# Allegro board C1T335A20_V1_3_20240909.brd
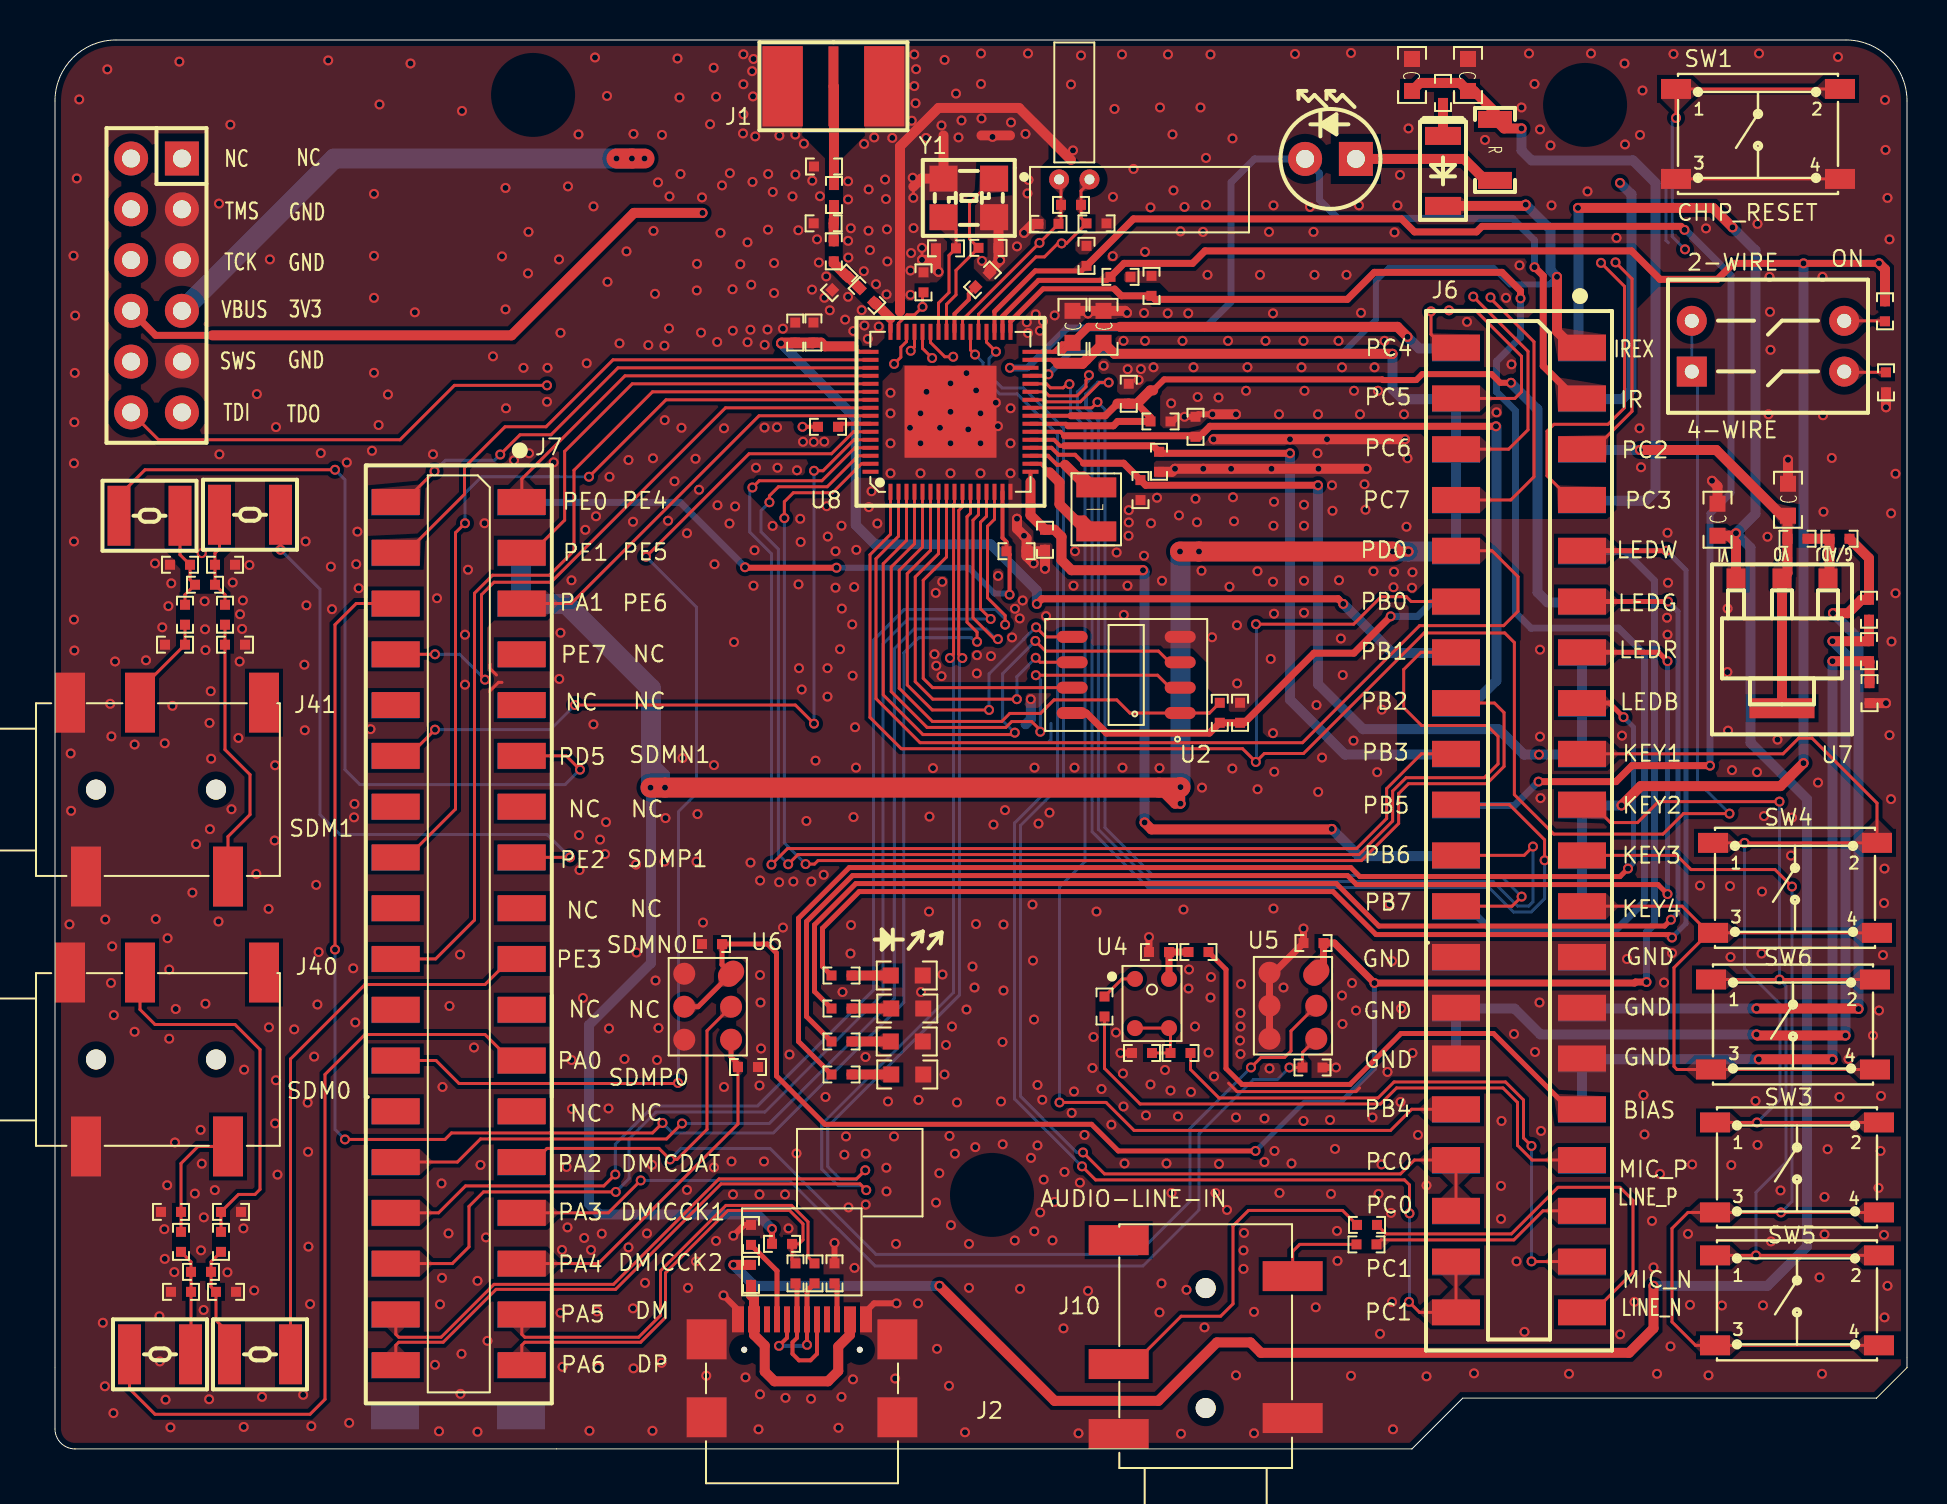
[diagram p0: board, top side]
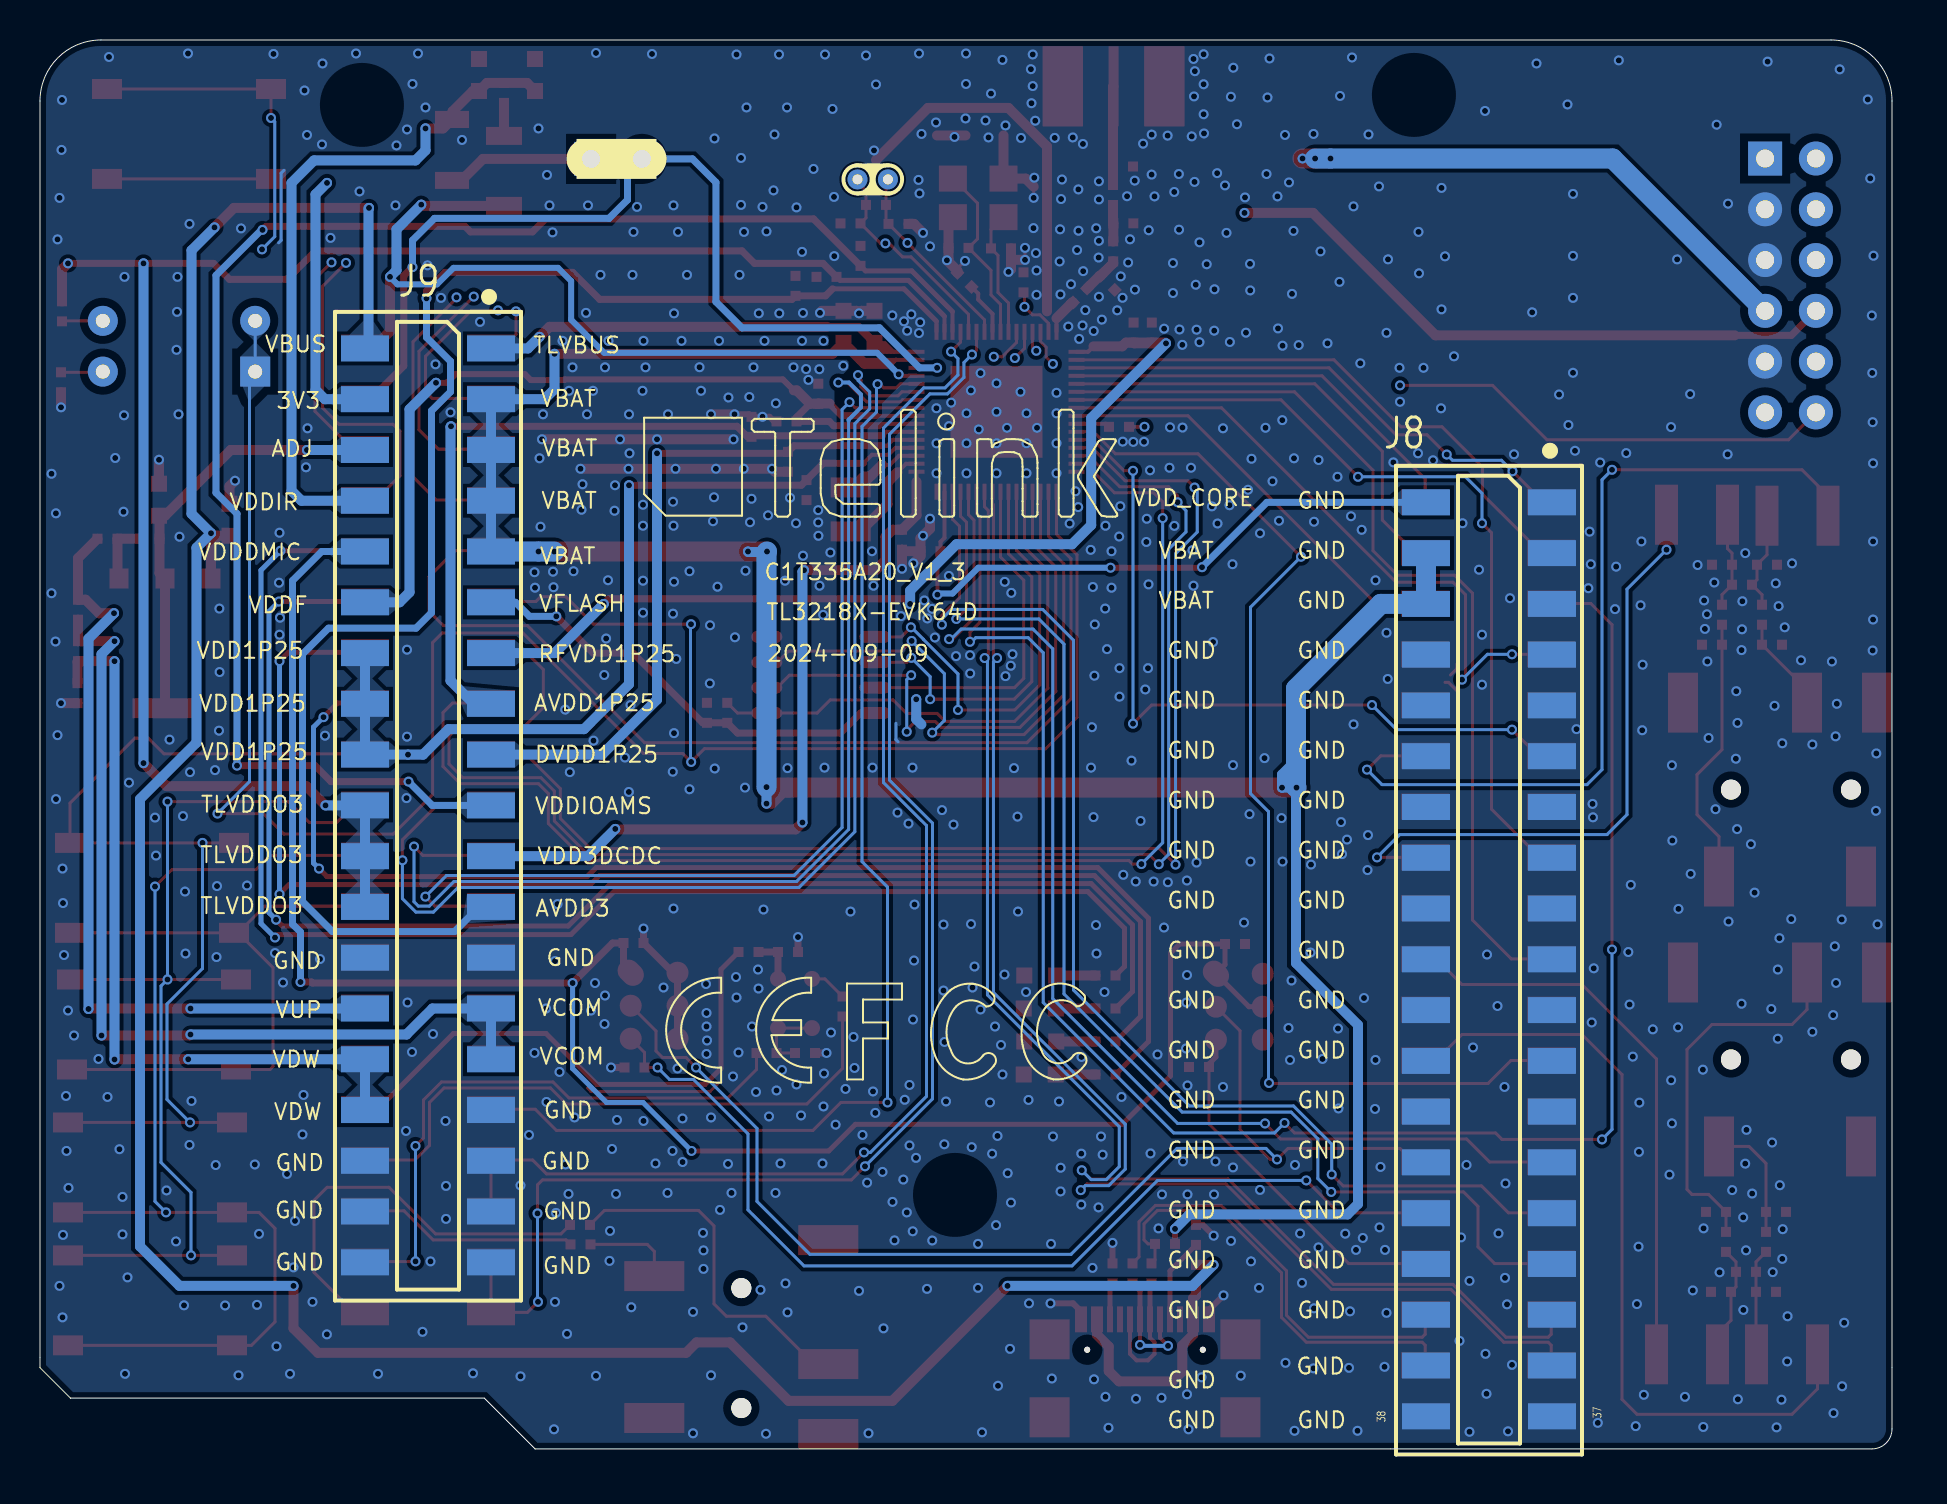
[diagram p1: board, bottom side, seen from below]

Outline 92.6 x 70.48 mm; copper layers: TOP, GND, POWER, BOTTOM. Coordinates in mm from the lower left corner of the outline.
Outline path: 0,67.43 0,1 arc(0.29,0.29) 1,0 67.85,0 70.39,2.54 91.08,2.54 92.6,4.06 92.6,67.43 arc(91.71,69.59) 89.55,70.48 3.05,70.48 arc(0.89,69.59) 0,67.43

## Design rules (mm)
constraint set DEFAULT: min track width 0.15, pair gap 0.1
net group DP1: nets TL_DM TL_DP
net group DP2: nets TL_PA5_DM TL_PA6_DP

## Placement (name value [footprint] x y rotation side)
C1  220pF  [0402]  40.6 57.7 135 top
C2  NC  [0402]  39.22 58.33 225 top
C3  1.5pF  [0402]  38.43 61.31 180 top
C5  NC  [0402]  44.55 60.06 0 top
C6  NC  [0402]  46.67 60.08 180 top
C8  0.1uF  [0402]  37.01 55.84 90 top
C9  2.2uF  [0402]  37.92 55.84 90 top
C12  2.2uF  [0402]  48.08 44.91 0 top
C15  1uF  [0402]  54.83 58.18 90 top
C18  1uF  [0402]  53.27 58.63 0 top
C21  NC  [0402]  52.08 61.31 180 top
C22  NC  [0402]  49.67 61.28 0 top
C23  1uF  [0402]  49.5 45.48 270 top
C24  1uF  [0402]  53.69 52.78 90 top
C26  NC/1uF  [0402]  55.27 51.4 0 top
C27  NC/1uF  [0402]  55.2 49.38 270 top
C28  4.7uF  [0402]  57.02 51.13 90 top
C30  1uF  [0402]  54.27 47.96 270 top
C33  1uF  [0402]  59.25 36.82 90 top
C36  10uF  [0603C]  70.65 68.73 270 top
C37  10uF  [0603C]  67.85 68.73 270 top
C38  10nF  [0402]  52.48 22.13 270 top
C39  1uF  [0402]  55.2 24.86 180 top
C41  0.1uF  [0402]  62.92 25.31 180 top
C42  0.1uF  [0402]  32.85 25.26 180 top
C43  10uF  [0603C]  83.12 46.48 90 top
C44  10uF  [0603C]  86.65 47.48 90 top
C45  2pF  [0402]  38.45 64.15 180 top
C47  1uF  [0402]  46.38 58.48 45 top
C48  10uF  [0603C]  52.42 56.13 90 top
C49  10uF  [0603C]  50.88 56.13 90 top
C50  1uF  [0402]  51.58 59.68 90 top
C51  10nF  [0402]  65.58 10.23 0 top
C52  10nF  [0402]  65.6 11.21 0 top
C53  1uF  [0402]  43.42 58.36 90 top
C69  NC  [0402]  8.55 7.86 180 top
C73  220nF  [0402]  7.3 8.86 180 top
C75  10pF  [0402]  8.8 11.86 180 top
C76  10pF  [0402]  5.8 11.86 180 top
C115  NC  [0402]  6.3 7.86 180 top
C116  NC  [0402]  8.5 44.23 0 top
C117  NC  [0402]  6.25 44.23 0 top
C118  10pF  [0402]  6 40.23 0 top
C119  10pF  [0402]  9 40.23 0 top
C120  220nF  [0402]  7.5 43.23 0 top
C121  10nF  [0402]  56.27 19.81 0 top
D1  Red  [0603-LED]  42.59 20.38 0 top
D2  White  [0603-LED]  42.59 23.68 0 top
D3  Green  [0603-LED]  42.61 22.03 0 top
D4  Blue  [0603-LED]  42.61 18.73 0 top
D5  LED_IR  [LED_TH_2P54MM_2PIN]  63.77 64.53 0 top
D6  1N4148  [SOD80]  69.4 63.93 270 top
J1  RFIN  [SMA-H]  38.92 68.16 90 top
J2  Type-C 16pin  [TYPE_C_CQ_105PWB]  37.35 5.48 0 top
J3  DIP_2X2  [DIPSWITCH_2P54_7P62_2X2]  85.65 55.16 270 top
J4  JTAG  [HDR254F-2X6X850]  6.35 51.85 90 top
J6  HEADER 20x2  [SMD254M-2X20_RX1_30Y2_40]  73.2 28.42 90 top
J7  HEADER 18X2  [SMD254M-2X18_RX1_30Y2_40]  20.19 20.7 90 top
J8  HEADER 19x2  [HDR2X19-2R54-SM-M]  20.15 24.45 90 bottom
J9  HEADER 19x2  [HDR2X19-2R54-SM-M]  73.2 32.15 90 bottom
J10  AIL1  [PJ-327]  57.53 -0.96 180 top
J40  PJ327  [PJ-327]  -0.95 19.48 90 top
J41  PJ327  [PJ-327]  -0.95 32.98 90 top
L1  2.2nH  [0402]  38.94 59.91 90 top
L2  6.8uH  [0805L_0717]  52.06 47 90 top
L3  2.4nH  [0402]  38.95 62.72 90 top
L15  150uH  [INDM3025X25]  5.25 4.73 0 top
L16  150uH  [INDM3025X25]  10.25 4.73 180 top
L17  150uH  [INDM3025X25]  9.75 46.73 180 top
L18  150uH  [INDM3025X25]  4.72 46.68 0 top
R1  NC  [0402]  50.8 62.23 180 top
R2  NC/1.5K  [0402]  36.35 10.26 180 top
R3  4.7K  [0402]  58.24 36.82 90 top
R4  33  [0402]  37.02 8.78 90 top
R5  5.1K  [0402]  34.8 10.71 270 top
R6  33  [0402]  37.98 8.78 90 top
R7  1K  [0402]  91.5 56.91 90 top
R8  1M  [0402]  91.55 53.36 270 top
R9  2R  [0402]  34.8 8.71 270 top
R10  5.1K  [0402]  38.98 8.78 270 top
R11  68R  [0402]  38.65 51.13 180 top
R12  1K  [0402]  39.33 20.38 0 top
R13  1K  [0402]  39.33 18.73 0 top
R14  1K  [0402]  39.33 23.68 0 top
R15  1K  [0402]  39.33 22.03 0 top
R16  1R  [1206R]  72 64.98 270 top
R17  0R  [0402]  69.4 67.83 270 top
R18  2.2K  [0402]  57.17 24.86 180 top
R27  100K  [0402]  62.88 19.08 180 top
R28  100K  [0402]  34.65 19.11 180 top
R29  430R  [0402]  89.22 45.53 0 top
R30  1.15K  [0402]  90.7 41.98 270 top
R31  787R  [0402]  90.7 39.91 270 top
R32  464R  [0402]  90.72 37.81 270 top
R33  1K  [0402]  87.12 45.53 180 top
R34  2.2K  [0402]  54.35 19.81 0 top
R40  33  [0402R]  6.3 10.36 90 top
R41  33  [0402R]  8.3 10.36 90 top
R42  33  [0402R]  8.5 41.73 270 top
R43  33  [0402R]  6.5 41.73 270 top
SW1  SW4PIN_4.5x4.5  [SW_6X6_SMD]  85.15 65.78 0 top
SW3  SW4PIN_4.5x4.5  [SW_6X6_SMD]  87.1 14.08 0 top
SW4  SW4PIN_4.5x4.5  [SW_6X6_SMD]  87 28.07 0 top
SW5  SW4PIN_4.5x4.5  [SW_6X6_SMD]  87.1 7.43 0 top
SW6  SW4PIN_4.5x4.5  [SW_6X6_SMD]  86.9 21.23 0 top
U2  P25Q16SUFWF  [W25X10_20_40BL]  53.56 38.72 90 top
U4  WMM7037AT2  [GA_BFA423_A83]  54.85 22.28 0 top
U5  WMM7047DTFN0  [DMIC_SPM0423HM4H-WB]  61.89 22.17 270 top
U6  WMM7047DTFN0  [DMIC_SPM0423HM4H-WB]  32.63 22.12 270 top
U7  LM1117-ADJ  [SOT-223]  86.35 40.05 180 top
U8  TL3218X  [QFN_8X8_64PIN_0P4_4P50X4P50]  44.77 51.88 90 top
Y1  24MHz-12pF-+/-10ppm  [OSCCC250X320X110]  45.69 62.58 270 top
Y2  NC/32.768K  [OSC_2X6]  50.97 67.51 270 top

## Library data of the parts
C1-C3 C21 C22 C45 = C1608_NC
C5 C6 C69 C115-C117 = C1005_NC
C8 C9 C12 C15 C18 C23 C24 C26-C28 C30 C33 C36-C39 C47-C53 C121 = C1005X5R1C104K
C41 C42 = C1005X5R1C104K_1
C43 = C1608X5R0J106M
C44 = C1608X5R1C105M
C73 C120 = C1005X5R1C224M
C75 C76 C118 C119 = C1005C0G1H100D
D1-D4 = 0603D_Green
D5 = Led_Th_3mm_1: User Part Number: partnum; Tolerance: RichardLC
D6 = Diode_1N4148
J1 = SMA_JACK_2
J2 = Type-C 16pin_0
J3 = HEADER 2X2_0: User Part Number: pn; Tolerance: RichardLC
J4 = HEADER 6X2: User Part Number: pn; Tolerance: RichardLC
J6 = HEADER 20x2/M: Tolerance: RichardLC
J7 = HEADER 18X2: Tolerance: RichardLC
J8 J9 = HEADER 19x2: Tolerance: RichardLC
J10 J40 J41 = PJ327_2
L1 L3 = MLK1608_000R
L2 = IND_0
L15-L18 = IND_150uH_3025
R1 R11 = RS0603K102JT
R2 = RS0402K152JT
R3 R7 R8 R18 R27 R28 R34 = RS0402K104JT
R4-R6 R9 R10 = RS0402K330JT: room: USB
R12-R15 R17 = RS0402K102JT
R16 = RS0402K102JT: User Part Number: pn; Tolerance: RichardLC
R29-R33 = RS0603K104JT
R40-R43 = RS0402K330JT
SW1 SW3-SW6 = SW_6X6_SMD_0
U2 = GD25LD40C_0: Tolerance: RichardLC
U4 = MULPS4CX-RM5_0
U5 U6 = LD1117/SO_0
U7 = XC62FP3302_0.3V_SOT-89
U8 = TL321X_0
Y1 = CRYSTAL4/SM_0: Tolerance: RichardLC
Y2 = OSC_2x6_2pin_16Mhz

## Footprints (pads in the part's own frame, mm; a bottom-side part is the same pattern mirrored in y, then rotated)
0402
  rect 0.5x0.5 smd: 1(-0.5,0) 2(0.5,0)
0402R
  rect 0.5x0.5 smd: 1(-0.5,0) 2(0.5,0)
0603-LED
  rect 0.8x0.8 smd: A(-0.8,0) C(0.8,0)
0603C
  rect 0.8x0.8 smd: 1(-0.8,0) 2(0.8,0)
0805L_0717
  rect 1x2 smd: 1(1.1,0) 2(-1.1,0)
1206R
  rect 0.85x1.7 smd: 1(-1.525,0) 2(1.525,0)
DIPSWITCH_2P54_7P62_2X2
  rect 1.5x1.5 hole 0.7: 1(1.27,-3.81)
  round 1.5 hole 0.7: 2(1.27,3.81) 3(-1.27,-3.81) 4(-1.27,3.81)
DMIC_SPM0423HM4H-WB
  round 1.1 smd: 1(-1.65,-1.17) 2(0,-1.17) 3(1.65,-1.17) 4(1.65,1.17) 5(0,1.17)
  oval 1.4x1.1 smd rot 135: 6(-1.65,1.17)
GA_BFA423_A83
  round 0.8 smd: 1(-0.85,1.23) 2(-0.85,-1.23) 3(0.85,-1.23) 4(0.85,1.23)
HDR2X19-2R54-SM-M
  rect 1.3x2.4 smd: 1(22.9,-3.15) 2(22.9,3.15) 3(20.36,-3.15) 4(20.36,3.15) 5(17.82,-3.15) 6(17.82,3.15) 7(15.28,-3.15) 8(15.28,3.15) 9(12.74,-3.15) 10(12.74,3.15) 11(10.2,-3.15) 12(10.2,3.15) 13(7.66,-3.15) 14(7.66,3.15) 15(5.12,-3.15) 16(5.12,3.15) 17(2.58,-3.15) 18(2.58,3.15) 19(0.04,-3.15) 20(0.04,3.15) 21(-2.5,-3.15) 22(-2.5,3.15) 23(-5.04,-3.15) 24(-5.04,3.15) 25(-7.58,-3.15) 26(-7.58,3.15) 27(-10.12,-3.15) 28(-10.12,3.15) 29(-12.66,-3.15) 30(-12.66,3.15) 31(-15.2,-3.15) 32(-15.2,3.15) 33(-17.74,-3.15) 34(-17.74,3.15) 35(-20.28,-3.15) 36(-20.28,3.15) 37(-22.82,-3.15) 38(-22.82,3.15)
HDR254F-2X6X850
  rect 1.7x1.7 hole 0.9: 1(12.7,0)
  round 1.7 hole 0.9: 2(12.7,2.54) 3(10.16,0) 4(10.16,2.54) 5(7.62,0) 6(7.62,2.54) 7(5.08,0) 8(5.08,2.54) 9(2.54,0) 10(2.54,2.54) 11(0,0) 12(0,2.54)
INDM3025X25
  rect 1.15x3 smd: 1(-1.525,0) 2(1.525,0)
LED_TH_2P54MM_2PIN
  rect 1.7x1.7 hole 0.9: A(1.27,0)
  round 1.7 hole 0.9: C(-1.27,0)
OSC_2X6
  round 1 hole 0.5: 1(4,0.76) 2(4,-0.76)
OSCCC250X320X110
  rect 1.3x1.4 smd: 1(-0.965,1.265) 2(-0.965,-1.265) 3(0.965,-1.265) 4(0.965,1.265)
PJ-327
  round 1 hole 1 unplated: (0,-3) (0,-9)
  rect 3x1.5 smd: 1(-4.35,-2.5) 2(4.35,-5.2) 3(-4.35,-9.6) 4(4.35,-11.4) 5(4.35,-1.7)
QFN_8X8_64PIN_0P4_4P50X4P50
  rect 0.8x0.2 smd: 1(-4,3) 2(-4,2.6) 3(-4,2.2) 4(-4,1.8) 5(-4,1.4) 6(-4,1) 7(-4,0.6) 8(-4,0.2) 9(-4,-0.2) 10(-4,-0.6) 11(-4,-1) 12(-4,-1.4) 13(-4,-1.8) 14(-4,-2.2) 15(-4,-2.6) 16(-4,-3) 33(4,-3) 34(4,-2.6) 35(4,-2.2) 36(4,-1.8) 37(4,-1.4) 38(4,-1) 39(4,-0.6) 40(4,-0.2) 41(4,0.2) 42(4,0.6) 43(4,1) 44(4,1.4) 45(4,1.8) 46(4,2.2) 47(4,2.6) 48(4,3)
  rect 0.2x0.8 smd: 17(-3,-4) 18(-2.6,-4) 19(-2.2,-4) 20(-1.8,-4) 21(-1.4,-4) 22(-1,-4) 23(-0.6,-4) 24(-0.2,-4) 25(0.2,-4) 26(0.6,-4) 27(1,-4) 28(1.4,-4) 29(1.8,-4) 30(2.2,-4) 31(2.6,-4) 32(3,-4) 49(3,4) 50(2.6,4) 51(2.2,4) 52(1.8,4) 53(1.4,4) 54(1,4) 55(0.6,4) 56(0.2,4) 57(-0.2,4) 58(-0.6,4) 59(-1,4) 60(-1.4,4) 61(-1.8,4) 62(-2.2,4) 63(-2.6,4) 64(-3,4)
  rect 4.6x4.6 smd: 65(0,0)
SMA-H
  rect 4x0.5 smd: 1(0,0)
  rect 4x2 smd: 2(0,-2.54) 3(0,2.54) 4(0,-2.54) 5(0,2.54)
SMD254M-2X18_RX1_30Y2_40
  rect 1.3x2.4 smd: 1(26.67,-3.15) 2(26.67,3.15) 3(24.13,-3.15) 4(24.13,3.15) 5(21.59,-3.15) 6(21.59,3.15) 7(19.05,-3.15) 8(19.05,3.15) 9(16.51,-3.15) 10(16.51,3.15) 11(13.97,-3.15) 12(13.97,3.15) 13(11.43,-3.15) 14(11.43,3.15) 15(8.89,-3.15) 16(8.89,3.15) 17(6.35,-3.15) 18(6.35,3.15) 19(3.81,-3.15) 20(3.81,3.15) 21(1.27,-3.15) 22(1.27,3.15) 23(-1.27,-3.15) 24(-1.27,3.15) 25(-3.81,-3.15) 26(-3.81,3.15) 27(-6.35,-3.15) 28(-6.35,3.15) 29(-8.89,-3.15) 30(-8.89,3.15) 31(-11.43,-3.15) 32(-11.43,3.15) 33(-13.97,-3.15) 34(-13.97,3.15) 35(-16.51,-3.15) 36(-16.51,3.15)
SMD254M-2X20_RX1_30Y2_40
  rect 1.3x2.4 smd: 1(26.67,-3.15) 2(26.67,3.15) 3(24.13,-3.15) 4(24.13,3.15) 5(21.59,-3.15) 6(21.59,3.15) 7(19.05,-3.15) 8(19.05,3.15) 9(16.51,-3.15) 10(16.51,3.15) 11(13.97,-3.15) 12(13.97,3.15) 13(11.43,-3.15) 14(11.43,3.15) 15(8.89,-3.15) 16(8.89,3.15) 17(6.35,-3.15) 18(6.35,3.15) 19(3.81,-3.15) 20(3.81,3.15) 21(1.27,-3.15) 22(1.27,3.15) 23(-1.27,-3.15) 24(-1.27,3.15) 25(-3.81,-3.15) 26(-3.81,3.15) 27(-6.35,-3.15) 28(-6.35,3.15) 29(-8.89,-3.15) 30(-8.89,3.15) 31(-11.43,-3.15) 32(-11.43,3.15) 33(-13.97,-3.15) 34(-13.97,3.15) 35(-16.51,-3.15) 36(-16.51,3.15) 37(-19.05,-3.15) 38(-19.05,3.15) 39(-21.59,-3.15) 40(-21.59,3.15)
SOD80
  rect 0.9x1.8 smd: A(-1.75,0) C(1.75,0)
SOT-223
  rect 0.95x1 smd: 1(-2.3,-3.495) 2(0,-3.495) 3(2.3,-3.495)
  rect 3.25x1 smd: 4(0,2.995)
SW_6X6_SMD
  rect 1.5x1 smd: 1(-4.1,2.25) 2(4.1,2.25) 3(-4.1,-2.25) 4(4.1,-2.25)
TYPE_C_CQ_105PWB
  round 0.3 hole 0.7 unplated: (-2.89,-0.52) (2.89,-0.52)
  rect 2x2 smd: 13(-4.77,0) 14(4.77,0) 15(-4.77,-3.9) 16(4.77,-3.9)
  rect 0.6x1.3 smd: A1B12(-3.2,1) A4B9(-2.4,1) B1A12(3.2,1) B4A9(2.4,1)
  rect 0.3x1.3 smd: A5(-1.25,1) A6(-0.25,1) A7(0.25,1) A8(1.25,1) B5(1.75,1) B6(0.75,1) B7(-0.75,1) B8(-1.75,1)
W25X10_20_40BL
  oval 0.6x1.55 smd: 1(-1.905,-2.7) 2(-0.635,-2.7) 3(0.635,-2.7) 4(1.905,-2.7) 5(1.905,2.7) 6(0.635,2.7) 7(-0.635,2.7) 8(-1.905,2.7)

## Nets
GND: C2.2 C3.2 C5.1 C6.1 C8.2 C9.2 C12.2 C15.2 C18.2 C21.1 C22.1 C23.2 C24.2 C26.2 C27.2 C28.2 C30.2 C33.2 C36.1 C37.1 C39.2 C41.2 C42.2 C43.2 C44.2 C45.2 C47.2 C48.2 C49.2 C50.2 C53.2 C69.1 C75.1 C76.2 C115.2 C116.2 C117.1 C118.1 C119.2 D1.C(CATHODE) D2.C(CATHODE) D3.C(CATHODE) D4.C(CATHODE) J1.2 J1.3 J1.4 J1.5 J2.13 J2.14 J2.15 J2.16 J2.A1B12 J2.B1A12 J4.3 J4.5 J4.9 J6.25 J6.26 J6.27 J6.28 J6.29 J6.30 J8.1 J8.3 J8.5 J8.7 J8.8 J8.9 J8.10 J8.11 J8.12 J8.13 J8.14 J8.15 J8.16 J8.17 J8.18 J8.19 J8.20 J8.21 J8.22 J8.23 J8.24 J8.25 J8.26 J8.27 J8.28 J8.29 J8.30 J8.31 J8.32 J8.33 J8.34 J8.35 J8.36 J8.37 J8.38 J9.25 J9.26 J9.31 J9.33 J9.34 J9.35 J9.36 J9.37 J9.38 J10.1 J10.5 J40.1 J40.5 J41.1 J41.5 R5.1 R8.2 R10.1 R27.1 R28.1 R32.2 R34.1 SW1.3 SW1.4 U2.4 U5.1 U5.2(SE) U5.3 U6.1 U6.3 U8.16 U8.65 Y1.2 Y1.4
VBAT_ADJ: C44.1 J9.6 R33.2 U7.2 U7.4(VOUT#4)
VBUS: C43.1 J4.8 J9.2 R9.1 U7.3
AIN_LINEIN_N: C52.2 J6.39
AIN_LINEIN_P: C51.2 J6.35
AIN_MIC_N: C121.2 J6.37
AIN_MIC_P: C38.2 J6.33
BEVK_SWS: J4.10 R11.2
DM: J2.A7 J2.B7 R6.1
DMICCK1: J7.29 R27.2 U5.4
DMICCK2: J7.31 R28.2 U6.4
DMICDAT: J7.27 U5.5 U6.5
DP: J2.A6 J2.B6 R4.1
EXT_3V3: J4.7 J9.4
LED_B: J6.15 R13.1
LED_G: J6.11 R15.1
LED_R: J6.13 R12.1
LED_W: J6.9 R14.1
MICBIAS: J6.31 R18.1
TL_ANT: C1.1 U8.48
TL_AVDD1P25: C28.1 J9.15 U8.22
TL_AVDD3: C15.1 J9.23 U8.33
TL_DM: J7.33 R6.2
TL_DP: J7.35 R2.1 R4.2
TL_DVDD1P25: C27.1 J9.17 U8.21
TL_FLASH: C33.1 J9.11 R3.1 U2.8
TL_IR: D5.C(CATHODE) J6.3 U8.30
TL_IR_EX_DIOD: D6.C J6.1 U8.29
TL_KEY1: J6.17 SW3.1 SW3.2 SW4.1 SW4.2
TL_KEY2: J6.19 SW5.1 SW5.2 SW6.1 SW6.2
TL_KEY3: J6.21 SW3.3 SW3.4 SW5.3 SW5.4
TL_KEY4: J6.23 SW4.3 SW4.4 SW6.3 SW6.4
TL_PA0: J7.24 U8.59
TL_PA1: J7.6 U8.11
TL_PA2: J7.28 U8.12
TL_PA3: J7.30 U8.14
TL_PA4: J7.32 U8.13
TL_PA5_DM: J7.34 U8.10
TL_PA6_DP: J7.36 U8.9
TL_PA7_SWS: R11.1 U8.58
TL_PB0: J3.1 J3.3 J6.12 U8.1
TL_PB1: J6.14 U8.62
TL_PB2: J6.16 U8.63
TL_PB3: J6.18 U8.61
TL_PB4: J6.32 U8.28
TL_PB5: J6.20 U8.27
TL_PB6: J6.22 U8.26
TL_PB7: J6.24 U8.25
TL_PC0_AUDIO_P: J6.34 J6.36 U8.36
TL_PC1_AUDIO_N: J6.38 J6.40 U8.38
TL_PC2_32K: C21.2 J6.5 R1.1 U8.37 Y2.1
TL_PC3_32K: C22.2 J6.7 R1.2 U8.39 Y2.2
TL_PC4_TDI: J4.12 J6.2 U8.43
TL_PC5_TDO: J4.11 J6.4 U8.44
TL_PC6_TMS: J4.4 J6.6 U8.46
TL_PC7_TCK: J4.6 J6.8 U8.45
TL_PD0: J6.10 U8.2
TL_PD5: J7.12 U8.60
TL_PE0: J7.2 U8.51
TL_PE1: J7.4 U8.50
TL_PE2: J7.16 U8.55
TL_PE3: J7.20 U8.54
TL_PE4: J7.1 U8.52
TL_PE5: J7.3 U8.53
TL_PE6: J7.5 U8.57
TL_PE7: J7.8 U8.56
TL_PF0_MOSI: U2.5 U8.6
TL_PF1_MCLK: U2.6 U8.7
TL_PF2_MSIO3: U2.7 U8.8
TL_PF3_MSCN: R3.2 U2.1 U8.5
TL_PF4_MISO: U2.2 U8.4
TL_PF5_MSIO2: U2.3(W\P\/IO2) U8.3
TL_RFVDD_1P25: C8.1 C9.1 J9.13 U8.49
TL_SDMN0: J7.19 L16.1
TL_SDMN1: J7.11 L18.1
TL_SDMP0: J7.23 L15.1
TL_SDMP1: J7.15 L17.1
TL_VBAT: C48.1 J8.4 J8.6 J9.3 J9.5 J9.7 J9.9 R2.2 U8.31
TL_VBUS: C49.1 J9.1 U8.32
TL_VDCDCF: C24.1 C26.1 J9.12 U8.23 U8.24
TL_VDD1P25: C30.1 J9.14 J9.16 J9.18 U8.20
TL_VDD3_DCDC: C23.1 J9.21 U8.17
TL_VDD_DMIC: C41.1 C42.1 J9.10 U5.6 U6.2(SE) U6.6
TL_VDD_IR: C36.2 C37.2 J9.8 R16.1 R17.1
TL_VDDCORE: C12.1 J8.2 U8.15
TL_VDDIO_AMS: C50.1 J9.19 U8.35
TL_VDDO3: C18.1 J9.20 J9.22 J9.24 R7.2 U8.34
TL_XC1: C5.2 U8.42 Y1.3
TL_XC2: C6.2 U8.41(XC2) Y1.1
USB_VBUS: J2.A4B9 J2.B4A9(VBUS#B4A9) R9.2
VCOM: J9.27 J9.29 R30.2 R31.1
VDW: J9.30 J9.32 R31.2 R32.1
VUP: J9.28 R29.2 R30.1
N20028206: R29.1 R33.1 U7.1
N20230742: D1.A R12.2
N20265888: C45.1 J1.1 L3.2
N20271178: D5.A R16.2
N20271193: D6.A R17.2
N20290987: L2.1 U8.19
N20305837: J2.A5 R5.2
N20305839: J2.B5 R10.2
N20310970: C1.2 C2.1 L1.1
N20310976: C3.1 L1.2 L3.1
N20338940: C53.1 SW1.1 SW1.2 U8.47
N20339485: C47.1 U8.40
N20340397: L2.2 U8.18
N20354870: C51.1 J10.3
N20355410: C39.1 R18.2 U4.4(VDD)
N20355416: C121.1 R34.2 U4.2 U4.3
N20355524: C38.1 U4.1
N20367047: C52.1 J10.2
N20394676: C116.1 C120.2 L17.2 R42.1
N20394683: C117.2 C120.1 L18.2 R43.1
N20394695: C119.1 J41.3 R42.2
N20394699: C118.2 J41.2 R43.2
N20394813: C73.2 C115.1 L15.2 R40.1
N20394820: C69.2 C73.1 L16.2 R41.1
N20394832: C76.1 J40.3 R40.2
N20394836: C75.2 J40.2 R41.2
N20397613: D2.A R14.2
N20397615: D3.A R15.2
N20397764: D4.A R13.2
N202309440: J3.2 R8.1
N202309690: J3.4 R7.1

Pads without a net: J2 A8 B8; J4 1 2; J7 7 9 10 13 14 17 18 21 22 25 26; J10 4; J40 4; J41 4; U8 64

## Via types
v1: diameter 0.5, hole 0.3, TOP to BOTTOM, 1088 vias

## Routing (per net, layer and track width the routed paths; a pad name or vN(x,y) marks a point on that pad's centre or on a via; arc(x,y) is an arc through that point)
GND: length 84.5
  TOP w0.15: 21.75,39.26 21.75,39.04 22.08,38.71 ; v1(42.92,62.58) 42.92,63.15 ; SW1.3 SW1.4 ; 65.23,18.05 65.05,17.87 59.1,17.87 58.68,18.29 ; 22.35,38.35 22.18,38.35 21.73,37.89 ; 46.73,58.93 46.73,59.05 v1(46.35,59.43) ; v1(43.35,59.48) v1(43.35,60.08)
  TOP w0.3: R5.1 34.46,11.21 v1(33.92,10.67) ; C26.2 55.89,51.4 56.12,51.63 v1(56.48,51.63) C28.2 57.15,51.76 v1(57.88,51.76) ; v1(42.08,7.28) 40.95,7.28 40.55,6.88 J2.B1A12 ; J2.A1B12 34.15,6.96 v1(33.42,7.68) ; R10.1 v1(38.98,10.31)
  TOP w0.35: R27.1 v1(64.05,19.08) ; C39.2 v1(54.7,25.61) ; U5.3 U5.2 U5.1 60.94,23.82 C41.2 v1(62.42,26.03) ; R34.1 v1(53.27,19.81)
  TOP w0.5: C12.2 49.42,44.91 C23.2 v1(49.5,44.03) ; C12.2 48.58,45.56 v1(48.45,45.68) 48.1,46.03 v1(48.1,46.53) ; C12.2 48.58,44.66 v1(48.93,44.3) ; C47.2 46.73,58.93 v1(47.26,59.46) 47.17,59.54 C6.1 47.17,61.4 Y1.4 ; 42.92,63.15 43.31,63.55 Y1.2 44.42,65.7 ; 44.05,59.48 C5.1 ; 44.05,59.48 43.35,59.48 v1(43.35,59.48) ; 44.05,59.48 44.05,59.01 v1(44.17,58.88) ; v1(48.45,60.83) 48.9,61.28 C22.1 ; v1(57.88,51.76) v1(59.05,51.76) ; v1(65.58,49.03) v1(63.17,49.03) v1(60.83,49.03) v1(58.8,49.03) v1(57.41,49.03) v1(56,49.03) 55.85,48.88 C27.2 ; v1(53.6,56.83) 53.5,56.93 C48.2 51.77,56.93 v1(51.65,56.81) 51.52,56.93 C49.2 ; v1(82.85,48.43) 83.12,48.16 C43.2 ; C44.2 v1(86.65,49.48) ; v1(67.5,50.51) v1(63.6,50.51) v1(61.75,50.51) v1(57.92,50.51) ; R32.2 v1(91.55,37.31) ; 46.33,65.7 47.75,65.7 ; R8.2 v1(91.55,52.11)
  BOTTOM w0.15: 80.4,63.96 80.55,63.82 80.55,60.46 80.67,60.33 ; 49.7,35.37 49.8,35.48 49.8,36.3
  BOTTOM w0.5: 48.53,36.25 48.79,36.5 v1(48.79,37.5)
  vias: v1(0.72,26.24) v1(0.78,34.79) v1(0.8,31.92) v1(0.93,59.69) v1(0.95,49.31) v1(0.95,45.4) v1(0.95,41.49) v1(1.01,56.7) v1(0.99,53.82) v1(0.97,51.36) v1(0.97,39.94) v1(1.09,63.56) v1(1.21,67.51) v1(2.39,6.31) v1(2.51,26.48) v1(2.49,3.13) v1(2.62,69.01) v1(2.76,37.27) v1(2.82,35.65) v1(2.8,23.31) v1(2.86,25.14) v1(2.94,21.7) v1(2.92,1.79) v1(3,39.39) v1(3.98,35.24) v1(3.98,20.87) v1(4.55,39.45) v1(5,44.3) v1(5.04,26.5) v1(5.22,6.64) v1(5.24,4.38) v1(5.36,41.1) v1(5.49,35.3) v1(5.47,10.99) v1(5.49,9.51) v1(5.53,2.46) v1(5.63,25.55) v1(5.61,13.19) v1(5.67,42.16) v1(5.71,23.98) v1(5.71,20.52) v1(5.81,43.3) v1(5.77,1.08) v1(5.87,37.17) v1(6.04,22.01) v1(6,15.33) v1(5.96,8.84) v1(6.22,69.4) v1(6.87,27.83) v1(6.99,12.77) v1(7.05,30.25) v1(7.34,44.81) v1(7.28,15.96) v1(7.34,14.27) v1(7.3,9.93) v1(7.44,11.58) v1(7.43,6.95) v1(7.48,42.4) v1(7.5,41) v1(7.52,39.96) v1(7.52,22.27) v1(7.73,36.32) v1(7.75,31) v1(7.71,2.48) v1(7.79,37.9) v1(7.81,34.53) v1(7.99,12.95) v1(8.2,62.29) v1(8.22,49.75) v1(8.17,26.38) v1(8.62,8.83) v1(8.77,66.24) v1(8.82,32) v1(8.89,43.34) v1(9.23,39.39) v1(9.17,35.56) v1(9.25,41.75) v1(9.39,42.44) v1(9.36,41.02) v1(9.42,11.03) v1(9.44,1.1) v1(9.46,18.97) v1(9.72,44.22) v1(9.96,7.93) v1(10.09,52.77) v1(10.07,28.76) v1(10.35,2.6) v1(10.74,59.5) v1(10.68,27.01) v1(10.7,21.09) v1(11.05,51.12) v1(11,34.2) v1(10.98,30.43) v1(11.04,18.44) v1(11,16.28) v1(11.13,13.72) v1(11.96,20.99) v1(12.41,2.7) v1(12.53,45.4) v1(12.47,39.23) v1(12.49,35.95) v1(12.57,42.2) v1(12.63,17.32) v1(12.65,14.86) v1(12.67,10.12) v1(12.75,7.25) v1(12.81,1.14) v1(12.96,19.62) v1(13.06,28.21) v1(13.12,22.23) v1(13.18,24.86) v1(13.29,49.81) v1(13.66,69.46) v1(13.79,44.13) v1(13.85,42.01) v1(14.59,49.34) v1(14.71,1.3) v1(14.91,24.04) v1(14.97,32.27) v1(14.95,31.59) v1(15.01,21.33) v1(15.12,45.89) v1(15.06,44.26) v1(15.18,43.06) v1(15.85,49.93) v1(15.78,36.01) v1(15.95,62.78) v1(15.95,59.68) v1(15.95,57.58) v1(15.95,53.83) v1(16.23,67.26) v1(16.18,51.22) v1(16.65,52.75) v1(17.77,69.31) v1(17.99,56.86) v1(18.9,49.76) v1(19,4.2) v1(19.1,42.56) v1(19.25,7.23) v1(19.2,0.88) v1(19.32,13.28) v1(19.35,8.56) v1(19.38,18.11) v1(19.73,22.16) v1(19.68,10.78) v1(20.25,24.73) v1(20.35,66.93) v1(20.32,4.76) v1(20.27,2.76) v1(20.5,40.73) v1(20.5,38.23) v1(20.65,43.98) v1(20.95,20.08) v1(21.12,8.41) v1(21.12,0.86) v1(21.27,14.21) v1(21.48,46.31) v1(21.55,10.58) v1(21.62,5.41) v1(21.9,54.66) v1(22.35,59.66) v1(22.52,63.08) v1(22.52,57.01) v1(22.55,52.06) v1(22.95,49.46) v1(23.43,54.08) v1(23.68,60.88) v1(23.65,58.81) v1(23.7,49.81) v1(24.62,54.08) v1(24.6,52.38) v1(24.93,49.35) v1(25.2,59.51) v1(25.21,38.52) v1(25.27,55.83) v1(25.27,40.83) v1(25.35,9.96) v1(25.27,6.81) v1(25.38,4.11) v1(25.57,14.11) v1(25.62,11.08) v1(25.65,63.16) v1(25.82,43.45) v1(25.82,19.46) v1(25.85,17.01) v1(26.18,65.76) v1(26.2,30.71) v1(26.23,28.96) v1(26.4,22.56) v1(26.52,45.98) v1(26.46,10.55) v1(26.59,54.31) v1(26.73,0.91) v1(26.8,9.96) v1(26.93,62.16) v1(26.92,36.25) v1(27,69.61) v1(27.05,46.66) v1(27.1,6.88) v1(27.25,30.48) v1(27.15,4.06) v1(27.34,10.77) v1(27.5,29.76) v1(27.6,67.68) v1(27.62,58.38) v1(27.55,31.36) v1(27.73,48.63) v1(27.7,21.03) v1(27.68,17.03) v1(28.23,55.31) v1(28.48,19.51) v1(28.57,59.91) v1(28.67,49.47) v1(28.68,10.08) v1(28.93,65.78) v1(28.9,46.38) v1(28.9,7.03) v1(28.93,4.03) v1(29.05,29.23) v1(29.07,24.83) v1(29.5,8.31) v1(29.6,10.78) v1(29.67,55.22) v1(29.85,14.21) v1(29.93,60.93) v1(29.9,49.56) v1(29.88,0.91) v1(30,57.78) v1(30.02,23.43) v1(30.1,19.46) v1(30.15,63.36) v1(30.18,21.06) v1(30.35,65.73) v1(30.32,4.31) v1(30.47,55.19) v1(30.49,51.46) v1(30.52,31.56) v1(30.48,29.38) v1(30.73,62.66) v1(30.7,56.05) v1(30.65,46.43) v1(30.98,48.41) v1(31.12,69.56) v1(31.23,67.61) v1(31.27,63.78) v1(31.32,51.08) v1(31.38,34.56) v1(31.6,45.81) v1(31.6,12.96) v1(31.65,8.06) v1(32.02,49.53) v1(32.1,59.28) v1(32.09,57.95) v1(32.12,31.76) v1(32.08,29.38) v1(32.05,9.38) v1(32.2,47.98) v1(32.3,55.84) v1(32.35,62.61) v1(32.4,26.33) v1(32.56,3.66) v1(32.75,66.27) v1(32.93,69.09) v1(32.95,34.21) v1(32.95,14.08) v1(32.98,44.26) v1(33.05,67.64) v1(33.11,55.37) v1(33.12,47.21) v1(33.05,10.41) v1(33.27,60.83) v1(33.35,63.21) v1(33.45,51.06) v1(33.45,18.11) v1(33.74,63.82) v1(33.72,46.29) v1(33.83,14.38) v1(33.88,58.01) v1(33.89,55.94) v1(33.95,40.36) v1(33.9,12.73) v1(34.01,47.15) v1(34.27,59.26) v1(34.42,69.77) v1(34.42,68.27) v1(34.42,66.77) v1(34.4,65.81) v1(34.52,3.58) v1(34.62,60.36) v1(34.63,55.36) v1(34.81,58.24) v1(34.77,55.99) v1(34.77,29.33) v1(34.92,69.53) v1(34.86,68.92) v1(34.9,67.66) v1(34.88,63.38) v1(34.92,43.18) v1(35.01,65.66) v1(34.98,44.96) v1(35.05,49.08) v1(35.25,23.71) v1(35.23,18.18) v1(35.23,12.73) v1(35.25,2.73) v1(35.17,0.98) v1(35.25,28.43) v1(35.27,22.33) v1(35.3,20.03) v1(35.45,14.38) v1(35.48,55.23) v1(35.47,51.09) v1(35.65,60.99) v1(35.63,56) v1(35.66,63.78) v1(35.89,62.88) v1(35.88,46.17) v1(35.95,59.32) v1(35.95,57.82) v1(36.1,51.11) v1(36.12,49.08) v1(36.22,65.7) v1(36.21,28.35) v1(36.39,56.04) v1(36.4,26.08) v1(36.5,12.73) v1(36.52,2.56) v1(36.73,19.73) v1(36.67,11.03) v1(36.88,62.66) v1(36.92,28.38) v1(37.02,65.75) v1(37.02,63.75) v1(37.1,48.96) v1(37.08,14.78) v1(37.16,60.96) v1(37.17,43.25) v1(37.2,39.06) v1(37.26,46.53) v1(37.28,45.37) v1(37.34,37.99) v1(37.45,65.29) v1(37.4,50.38) v1(37.57,31.41) v1(37.81,28.38) v1(37.8,2.51) v1(37.86,63.44) v1(37.85,57.99) v1(37.94,50.37) v1(38.02,34.43) v1(38.1,60.51) v1(38.25,62.66) v1(38.19,59.35) v1(38.44,28.72) v1(38.47,57.58) v1(38.46,50.39) v1(38.52,17.61) v1(38.56,58.65) v1(38.58,47.16) v1(38.64,45.64) v1(38.62,39.06) v1(38.62,37.63) v1(38.74,56.96) v1(39.02,44.91) v1(39.02,43.08) v1(39.25,40.01) v1(39.17,1.06) v1(39.33,46.18) v1(39.34,42.04) v1(39.33,2.61) v1(39.38,22.86) v1(39.51,56.49) v1(39.47,14.72) v1(39.55,15.63) v1(39.65,63.41) v1(39.66,62.5) v1(39.66,60.43) v1(39.67,59.6) v1(39.65,57.63) v1(39.67,12.08) v1(39.79,61.06) v1(39.8,26.21) v1(39.77,24.78) v1(39.92,55.92) v1(39.86,41.24) v1(39.88,38.68) v1(39.92,31.61) v1(39.9,3.48) v1(39.96,43.12) v1(40,36.1) v1(39.98,9.06) v1(40.06,44.97) v1(40.05,34.08) v1(40.34,56.97) v1(40.44,58.92) v1(40.45,65.28) v1(40.47,56.2) v1(40.52,19.61) v1(40.54,14.77) v1(40.54,12.22) v1(40.64,55.53) v1(40.68,63.01) v1(40.67,60.94) v1(40.75,59.97) v1(40.69,47.11) v1(40.83,47.91) v1(40.96,65.6) v1(41.05,58.26) v1(41.12,46.29) v1(41.19,56.14) v1(41.5,63.5) v1(41.55,62.52) v1(41.6,61.01) v1(41.62,59.4) v1(41.58,57.75) v1(41.65,17.38) v1(41.57,14.07) v1(41.57,12.88) v1(41.77,52.83) v1(41.77,51.81) v1(41.77,50.31) v1(41.77,48.81) v1(41.86,65.58) v1(41.95,15.63) v1(42.01,3.52) v1(42.05,10.26) v1(42.84,66.44) v1(42.8,59.82) v1(42.77,58.95) v1(42.77,57.73) v1(42.75,51.08) v1(42.89,63.59) v1(42.93,61.07) v1(42.96,69.76) v1(42.96,68.17) v1(43.03,67.32) v1(43.05,69.02) v1(43.15,7.28) v1(43.17,17.46) v1(43.27,51.81) v1(43.27,50.31) v1(43.27,48.81) v1(43.3,22.86) v1(43.55,65.58) v1(43.58,52.88) v1(43.73,31.63) v1(43.7,26.88) v1(43.9,34.06) v1(44.04,42.82) v1(43.98,39.76) v1(44.06,39.18) v1(44.05,12.32) v1(44.1,5.01) v1(44.25,51.08) v1(44.22,13.79) v1(44.33,66.2) v1(44.33,38.66) v1(44.36,43.37) v1(44.38,23.73) v1(44.48,69.48) v1(44.48,18.73) v1(44.55,20.21) v1(44.73,15.66) v1(44.7,3.16) v1(44.77,53.31) v1(44.77,51.88) v1(44.77,50.31) v1(44.77,48.81) v1(44.8,11.19) v1(44.85,21.13) v1(45,14.77) v1(45.05,67.8) v1(45.1,17.33) v1(45.17,65.61) v1(45.33,66.45) v1(45.5,0.83) v1(45.57,53.82) v1(45.58,21.98) v1(45.66,51) v1(45.7,10.26) v1(45.7,8.06) v1(45.88,24.13) v1(45.98,23.08) v1(46.01,15.1) v1(46.05,52.95) v1(46.1,39.71) v1(46.09,38.79) v1(46.05,26.26) v1(46.3,69.81) v1(46.3,68.28) v1(46.33,66.56) v1(46.27,51.81) v1(46.27,50.31) v1(46.27,48.81) v1(46.8,39.66) v1(46.88,65.63) v1(46.92,31.23) v1(47.04,52.34) v1(47.15,51.16) v1(47.16,43.67) v1(47.3,17.38) v1(47.42,26.23) v1(47.42,22.93) v1(47.38,20.36) v1(47.38,15.24) v1(47.5,31.96) v1(47.8,66.36) v1(47.78,52.06) v1(47.77,50.31) v1(47.77,48.81) v1(47.85,40.59) v1(48,42.02) v1(47.99,10.42) v1(48.1,60.16) v1(48.23,41.54) v1(48.25,8.01) v1(48.38,42.44) v1(48.52,65.78) v1(48.65,69.81) v1(48.62,62.81) v1(48.59,56.36) v1(48.67,63.48) v1(48.65,55.82) v1(48.8,14.56) v1(48.88,27.23) v1(48.9,24.43) v1(49.03,56.76) v1(48.98,34.08) v1(48.95,21.48) v1(48.96,10.89) v1(49.12,18.21) v1(49.12,15.18) v1(49.24,55.93) v1(49.17,31.28) v1(49.26,11.83) v1(49.4,56.41) v1(49.36,17.46) v1(49.44,13.47) v1(49.55,41.66) v1(49.73,31.83) v1(49.88,10.43) v1(49.98,56.7) v1(49.98,12.36) v1(50.42,6.03) v1(50.48,13.86) v1(50.8,68.26) v1(50.83,16.81) v1(50.9,64.95) v1(50.92,43.18) v1(51,44.91) v1(50.98,34.08) v1(50.95,17.88) v1(51.24,13.32) v1(51.17,0.78) v1(51.3,69.7) v1(51.48,15.71) v1(51.65,7.91) v1(51.92,20.61) v1(51.88,19.06) v1(52.08,26.88) v1(52.33,18.01) v1(52.44,54.18) v1(52.82,16.22) v1(52.9,62.63) v1(52.89,59.67) v1(52.98,67.03) v1(53.05,20.83) v1(53.08,44.84) v1(53.35,69.76) v1(53.42,55.43) v1(53.44,41.72) v1(53.38,34.08) v1(53.4,18.78) v1(53.42,17.13) v1(53.48,14.28) v1(53.63,54.01) v1(53.62,43.18) v1(53.69,46.96) v1(53.69,46.35) v1(53.68,45.68) v1(53.92,64.03) v1(54.18,53.48) v1(54.29,54.02) v1(54.5,59.88) v1(54.45,56.82) v1(54.5,55.43) v1(54.45,44.68) v1(54.55,16.68) v1(54.77,62.11) v1(54.8,46.31) v1(54.77,18.23) v1(54.92,54.11) v1(55.1,47.58) v1(55.25,67.11) v1(55.23,34.06) v1(55.23,6.83) v1(55.33,8.28) v1(55.35,43.43) v1(55.5,18.96) v1(55.65,69.76) v1(55.64,56.81) v1(55.58,14.28) v1(55.81,52.31) v1(55.77,17.93) v1(55.83,12.81) v1(55.88,65.76) v1(55.92,62.96) v1(56.15,16.63) v1(56.2,46.7) v1(56.27,60.91) v1(56.3,0.76) v1(56.38,55.43) v1(56.42,26.98) v1(56.48,62.13) v1(56.58,7.96) v1(56.66,56.81) v1(56.7,23.98) v1(56.67,23.03) v1(56.8,17.86) v1(56.92,54.11) v1(57.02,47.53) v1(57,21.13) v1(57.13,52.62) v1(57.1,46.36) v1(57.27,67.11) v1(57.33,43.93) v1(57.4,60.88) v1(57.35,33.08) v1(57.55,64.58) v1(57.55,62.23) v1(57.48,6.08) v1(57.62,58.73) v1(57.67,19.83) v1(57.77,69.76) v1(57.8,23.61) v1(57.77,22.58) v1(57.85,40.6) v1(57.95,18.63) v1(58.02,12.81) v1(58.18,52.59) v1(58.2,14.26) v1(58.65,55.43) v1(58.6,11.96) v1(58.73,43.13) v1(58.88,65.56) v1(58.9,47.61) v1(58.87,34.04) v1(58.95,46.41) v1(59.05,16.58) v1(59.05,3.68) v1(59.1,41.2) v1(59.11,38.29) v1(59.25,20.43) v1(59.3,23.26) v1(59.27,21.81) v1(59.27,21.13) v1(59.27,19.76) v1(59.42,9.93) v1(59.42,9.01) v1(59.55,52.93) v1(59.45,10.81) v1(59.62,54.11) v1(59.95,6.86) v1(59.95,0.78) v1(60.12,43.91) v1(60.13,33) v1(60.25,58.73) v1(60.52,55.43) v1(60.48,16.53) v1(60.47,14.35) v1(60.7,60.88) v1(60.73,19.03) v1(60.79,39.52) v1(60.92,62.21) v1(60.9,56.81) v1(60.92,46.18) v1(60.9,43.38) v1(60.9,35.81) v1(60.92,27.03) v1(60.95,47.38) v1(60.95,41.78) v1(60.96,33.87) v1(60.98,14.91) v1(61.2,51.76) v1(61.23,12.81) v1(61.42,23.08) v1(61.83,14.28) v1(62,69.78) v1(62.33,54.11) v1(62.42,55.43) v1(62.42,16.41) v1(62.48,52.93) v1(62.45,47.23) v1(62.45,46.18) v1(62.45,43.43) v1(62.45,41.83) v1(62.75,62.13) v1(62.92,60.88) v1(62.98,58.73) v1(63.04,7.09) v1(63.15,51.76) v1(63.12,49.81) v1(63.08,37.21) v1(63.16,32.86) v1(63.35,34.58) v1(63.75,16.46) v1(63.8,12.76) v1(63.85,48.21) v1(63.88,46.93) v1(64,15.01) v1(64.1,10.91) v1(64.12,9.41) v1(64.17,55.43) v1(64.2,43.46) v1(64.29,40.54) v1(64.35,54.11) v1(64.39,38.71) v1(64.35,22.68) v1(64.38,21.26) v1(64.58,58.73) v1(64.8,69.83) v1(64.8,3.66) v1(64.92,35.43) v1(64.85,23.31) v1(64.95,52.93) v1(65.05,21.93) v1(65.2,62.21) v1(65.25,51.76) v1(65.3,56.83) v1(65.47,48.26) v1(65.53,46.98) v1(65.92,43.91) v1(65.88,16.58) v1(65.97,54.11) v1(66.15,52.93) v1(66.11,33.85) v1(66.17,12.76) v1(66.25,5.76) v1(66.34,36.98) v1(66.33,14.23) v1(66.47,55.43) v1(66.62,18.86) v1(66.72,27.26) v1(66.8,11.81) v1(66.92,43.11) v1(66.85,24.41) v1(66.85,7.36) v1(66.9,0.98) v1(66.97,60.86) v1(66.95,43.88) v1(67.12,62.21) v1(67.25,63.73) v1(67.3,22.03) v1(67.28,17.36) v1(67.45,51.76) v1(67.62,49.56) v1(67.58,46.13) v1(67.67,66.06) v1(67.88,43.86) v1(67.85,43.08) v1(67.88,19.81) v1(68.15,15.71) v1(68.58,13.18) v1(68.58,3.63) v1(70.6,56.38) v1(70.95,3.78) v1(71.5,65.48) v1(72.08,51.86) v1(72.33,16.41) v1(72.3,13.16) v1(72.3,11.51) v1(72.55,57.58) v1(72.83,54.26) v1(72.95,20.76) v1(73.08,9.38) v1(73.22,59.21) v1(73.33,67.11) v1(73.47,5.86) v1(73.7,69.81) v1(73.97,68.28) v1(74,19.86) v1(74.25,66.01) v1(74.25,39.98) v1(74.25,35.63) v1(74.22,22.33) v1(74.28,32.56) v1(74.3,15.91) v1(74.78,65.2) v1(74.83,62.21) v1(75.7,3.76) v1(76.62,62.91) v1(76.8,69.81) v1(78.08,60.58) v1(78.26,5.73) v1(78.35,35.68) v1(78.47,69.31) v1(78.5,65.26) v1(78.6,24.51) v1(78.97,7.36) v1(79.25,65.73) v1(79.22,51.06) v1(79.3,49.11) v1(79.38,67.95) v1(79.42,17.71) v1(79.47,15.73) v1(79.85,11.41) v1(79.92,9.08) v1(80.1,3.76) v1(80.25,13.76) v1(80.45,23.33) v1(80.62,45.83) v1(80.6,41.58) v1(80.62,40.73) v1(80.65,43.33) v1(80.85,24.81) v1(80.78,5.13) v1(80.92,69.78) v1(81.65,10.76) v1(81.75,7.21) v1(81.86,14.23) v1(82.25,28.18) v1(82.55,61.06) v1(82.67,3.68) v1(83.34,7.17) v1(83.63,42.04) v1(83.62,38.86) v1(83.65,35.93) v1(83.85,33.96) v1(83.75,28.16) v1(83.78,24.61) v1(83.81,14.2) v1(85.03,17.41) v1(85.12,61.28) v1(85.1,33.86) v1(85.12,15.21) v1(85.2,69.81) v1(85.35,27.88) v1(85.33,24.78) v1(85.4,7.18) v1(85.45,31.66) v1(85.62,45.63) v1(85.72,58.63) v1(85.67,51.76) v1(85.75,56.88) v1(85.78,54.98) v1(85.8,10.38) v1(86.12,35.48) v1(86.28,12.93) v1(86.85,31.58) v1(86.8,29.68) v1(88.15,33.33) v1(88.22,8.58) v1(88.35,3.76) v1(88.38,58.63) v1(88.4,51.71) v1(88.42,46.88) v1(88.47,12.61) v1(88.47,10.73) v1(88.63,14.99) v1(88.84,49.57) v1(89.15,69.63) v1(89.22,17.61) v1(89.67,19.51) v1(90.9,20.68) v1(91.2,21.93) v1(91.17,13.06) v1(91.3,17.66) v1(91.28,14.91) v1(91.4,24.71) v1(91.5,67.48) v1(91.53,64.98) v1(91.47,29.03) v1(91.45,27.31) v1(91.45,10.71) v1(91.47,6.58) v1(91.62,62.58) v1(91.62,8.16) v1(91.72,60.51) v1(91.72,35.71) v1(91.8,46.8) v1(91.83,40.39) v1(91.8,32.51) v1(92.03,48.78) v1(92.03,42.81)
VBAT_ADJ: length 21.4
  TOP w0.5: U7.4 U7.2 86.62,43.82 R33.2 86.62,46.66 C44.1 86.35,46.68 83.06,49.97 v1(79.25,49.97)
  BOTTOM w0.5: J9.6 v1(79.25,49.97)
VBUS: length 213.4
  TOP w0.35: J4.8 5.03,55.71 7.87,55.71
  TOP w0.5: v1(44.23,8.16) 49.98,2.4 55.17,2.4 58.09,5.33 59.77,5.33 60.29,4.81 78.7,4.81 79.92,6.03 v1(79.92,8.16) ; 7.87,55.71 22.82,55.71 28.95,61.83 v1(32.38,61.83) ; R9.1 v1(33.92,9.21) ; 83.7,45.68 84.05,45.33 U7.3 ; 83.7,45.68 C43.1 ; 83.7,45.68 83.92,45.68 v1(84.05,45.81) ; v1(83.88,61.11) 82.9,62.08 v1(76.15,62.08)
  POWER w0.5: v1(32.38,61.83) 53.33,61.83 58.17,66.68 66.1,66.68 69.89,62.89 75.34,62.89 v1(76.15,62.08)
  BOTTOM w0.5: v1(33.92,9.21) 34.98,8.16 v1(44.23,8.16) ; v1(79.92,8.16) 85.62,8.16 87.6,10.13 87.6,32.51 84.78,35.33 84.78,45.08 v1(84.05,45.81) 85.03,46.78 85.03,59.96 v1(83.88,61.11) ; v1(76.15,62.08) 76.17,62.06 76.17,55.23 J9.2
AIN_LINEIN_N: length 21.2
  TOP w0.15: J6.39 76.9,6.83 78.9,8.83 78.9,12.43 78.25,13.09 75.15,13.09 72.82,10.76 66.55,10.76 C52.2
AIN_LINEIN_P: length 11
  TOP w0.15: C51.2 66.3,10.46 72.94,10.46 74.4,11.91 J6.35
AIN_MIC_N: length 29.5
  TOP w0.15: J6.37 73.84,9.37 v1(73.83,9.38) ; v1(73.83,15.16) 73.42,15.56 73.42,17.45 72.52,18.36 66.95,18.36 66.15,17.56 58.2,17.56 56.77,18.98 C121.2
  BOTTOM w0.15: v1(73.83,15.16) v1(73.83,9.38)
AIN_MIC_P: length 30.3
  TOP w0.15: C38.2 52.48,19.03 54.25,17.26 66.28,17.26 67.08,18.06 72.4,18.06 73.12,17.33 73.12,15.18 73.86,14.45 J6.33
BEVK_SWS: length 38
  TOP w0.2: v1(37.38,51.13) R11.2
  POWER w0.15: J4.10 4.97,53.22 4.97,51.26 5.75,50.48 21.04,50.48 21.74,51.18 23.55,51.18 24.25,50.48 36.73,50.48 v1(37.38,51.13)
DM: length 6.1
  TOP w0.2: v1(36.2,5.16) 36.6,5.56 J2.B7 ; J2.A7 v1(37.6,5.2)
  TOP w0.25: J2.A7 37.6,7.91 R6.1
  BOTTOM w0.2: v1(36.2,5.16) 37.55,5.16 v1(37.6,5.2)
DMICCK1: length 49.5
  TOP w0.15: U5.4 62.38,19.83 R27.2 v1(61.72,19.08) ; v1(29.29,13.43) 27.67,11.81 J7.29
  BOTTOM w0.15: v1(61.72,19.08) 61.12,18.48 59.93,18.48 57.2,15.76 57.2,11.96 54.4,9.16 41,9.16 36.73,13.43 v1(29.29,13.43)
DMICCK2: length 18.1
  TOP w0.15: J7.31 27.16,9.27 34.15,16.26 R28.2
  TOP w0.25: U6.4 33.8,19.6 34.15,19.26 R28.2
DMICDAT: length 59.6
  TOP w0.15: U6.5 32.6,20.92 32.6,15.98 31.1,14.48 v1(30.75,14.48) 30.2,15.03 24.6,15.03 23.92,14.35 J7.27 ; U5.5 61.8,20.91 61.8,19.91 61.48,19.58 60.3,19.58 v1(59.8,19.08)
  BOTTOM w0.15: v1(59.8,19.08) 56.75,16.03 56.75,12.38 54.1,9.73 41.05,9.73 35.75,15.03 31.3,15.03 v1(30.75,14.48)
DP: length 6.9
  TOP w0.2: J2.A6 37.1,5.56 36.88,5.33 36.88,4.76 37.2,4.43 37.77,4.43 38.1,4.76 J2.B6
  TOP w0.25: J2.A6 37.1,8.21 R4.1
EXT_3V3: length 94
  TOP w1: v1(28.07,64.55) v1(28.84,64.55) v1(29.48,64.55)
  POWER w0.5: v1(28.84,64.55) v1(28.07,64.55) ; v1(29.48,64.55) 48.67,64.55 52.27,68.16 67.15,68.16 71.15,64.16 77.42,64.16 v1(78.25,63.33)
  POWER w1: v1(29.48,64.55) v1(28.84,64.55)
  BOTTOM w0.5: v1(78.25,63.33) 78.83,62.76 78.83,52.98 78.35,52.51 J9.4
  BOTTOM w1: J4.7 13.96,64.55 v1(28.07,64.55) v1(28.84,64.55)
LED_B: length 61.6
  TOP w0.25: J6.15 77.72,37.31 v1(78.42,36.61) ; R13.1 37.17,20.38 37.17,26.54 39.71,29.08 64.79,29.08 65.24,28.63 78.25,28.63 v1(78.65,29.03)
  BOTTOM w0.25: v1(78.42,36.61) 78.92,36.11 78.92,29.31 v1(78.65,29.03)
LED_G: length 69.8
  TOP w0.25: J6.11 v1(80.65,42.39) ; R15.1 37.98,22.88 37.98,26.21 40.04,28.28 64.07,28.28 66.19,26.16 80.48,26.16 v1(80.8,26.47)
  BOTTOM w0.25: v1(80.65,42.39) 81.15,41.89 81.15,26.83 v1(80.8,26.47)
LED_R: length 67
  TOP w0.25: v1(80.62,27.76) 80.15,28.23 65.08,28.23 64.62,28.68 39.88,28.68 37.58,26.38 37.58,21.63 R12.1 ; v1(80.62,39.41) 80.18,39.85 J6.13
  BOTTOM w0.25: v1(80.62,27.76) v1(80.62,39.41)
LED_W: length 71
  TOP w0.25: R14.1 38.38,24.13 38.38,26.05 40.21,27.88 63.9,27.88 66.05,25.73 80.7,25.73 v1(80.85,25.58) ; J6.9 v1(80.58,44.93)
  BOTTOM w0.25: v1(80.58,44.93) 81.55,43.96 81.55,26.28 v1(80.85,25.58)
MICBIAS: length 26.9
  TOP w0.25: R18.1 58.55,23.98 58.55,19.03 59.35,18.23 64.75,18.23 67.3,20.78 71.92,20.78 75.72,16.99 J6.31
TL_ANT: length 2
  TOP w0.2: U8.48 41.77,56.56
  TOP w0.5: 41.06,57.27 40.99,57.35 C1.1 41.03,57.27 41.06,57.27 ; 41.06,57.27 41.77,56.56
TL_AVDD1P25: length 38.8
  TOP w0.2: 50.48,50.68 50.27,50.88 U8.22
  TOP w0.35: 50.48,50.68 56.98,50.68 C28.1 57.23,50.63 57.75,51.16 v1(72.05,51.16)
  BOTTOM w0.5: J9.15 70.91,37.27 72.08,38.43 72.08,51.13 v1(72.05,51.16)
TL_AVDD3: length 75.1
  TOP w0.2: U8.33 47.77,56.41
  TOP w0.25: 47.77,56.41 49.4,58.03 52.98,58.03
  TOP w0.35: v1(73.28,57.56) 73.28,57.93 72.35,58.86 65.97,58.86 64.62,57.51 55,57.51 C15.1 53.33,57.68 52.98,58.03
  BOTTOM w0.35: v1(73.28,57.56) 73.28,55.61 72.08,54.41 72.08,52.88 73.03,51.93 73.03,41.83 73.8,41.06 78.17,41.06 79.47,39.76 79.47,27.38 77.97,25.88 71.88,25.88 70.65,27.11 J9.23
TL_DM: length 22
  TOP w0.15: R6.2 37.65,9.61 37.65,11.36 36.83,12.18 33.55,12.18 30.27,8.91 30.27,6.68 29.18,5.59 23.49,5.59 23.34,5.73 J7.33
TL_DP: length 21.9
  TOP w0.15: J7.35 23.34,5.19 23.49,5.34 29.28,5.34 30.52,6.58 30.52,8.81 33.65,11.93 36.73,11.93 37.4,11.26 37.4,10.46 37.2,10.26 R2.1 36.85,9.46 R4.2
TL_DVDD1P25: length 35
  TOP w0.2: U8.21 49.95,50.48 50.25,50.18 50.48,50.18
  TOP w0.35: 50.48,50.18 54.9,50.18 C27.1 55.27,49.81 v1(61.75,49.81)
  BOTTOM w0.5: v1(61.75,49.81) 61.75,37.48 64.5,34.73 J9.17
TL_FLASH: length 22.3
  TOP w0.35: U2.8 51.57,36.81 52.58,35.81 57.72,35.81 R3.1 C33.1 59.47,36.32 62.95,39.81 64.94,39.81 v1(66.78,41.65)
  BOTTOM w0.35: v1(66.78,41.65) 68.13,41.65 68.83,42.35 J9.11
TL_IR: length 46.6
  TOP w0.2: U8.30 v1(47.74,54.08)
  TOP w0.35: J6.3 76.03,52.55 74.41,54.17 74.41,58.68 v1(73.97,59.12)
  BOTTOM w0.35: v1(47.74,54.08) 48.62,54.08 50.62,56.08 57.5,56.08 58.8,57.38 58.8,63.36 59.98,64.53 D5.C 63.23,63.81 63.23,62.48 64.15,61.56 72.88,61.56 73.97,60.46 v1(73.97,59.12)
TL_IR_EX_DIOD: length 42.9
  TOP w0.2: U8.29 49.59,53.68 v1(49.67,53.76)
  TOP w0.5: v1(73.54,62.24) 73.47,62.18 D6.C ; v1(75.1,58.63) 75.1,55.91 75.91,55.09 J6.1
  BOTTOM w0.3: v1(49.67,53.76) 50.74,54.83 64.39,54.83 66.04,56.49 66.04,58.42 66.7,59.08 71.92,59.08 72.75,58.26 74.72,58.26 v1(75.1,58.63)
  BOTTOM w0.5: v1(73.54,62.24) 74.78,61.01 74.78,58.96 v1(75.1,58.63)
TL_KEY1: length 50
  TOP w0.15: J6.17 86.4,34.77 87.19,35.56 87.85,35.56 91.1,32.31 SW4.2 v1(84.47,30.32) SW4.1 ; SW3.1 v1(85.1,16.33) SW3.2
  BOTTOM w0.15: v1(84.47,30.32) 84.47,24.03 86.25,22.26 86.25,17.48 v1(85.1,16.33)
TL_KEY2: length 50.5
  TOP w0.15: SW6.1 v1(86.22,23.48) SW6.2 ; SW5.2 v1(85.05,9.68) SW5.1 ; v1(86.22,32.38) 80.17,32.38 79.12,31.33 77.78,31.33 76.88,32.23 J6.19
  BOTTOM w0.15: v1(85.05,9.68) 85.05,12.83 86.55,14.33 86.55,23.16 v1(86.22,23.48) v1(86.22,32.38)
TL_KEY3: length 53.9
  TOP w0.15: SW5.4 SW5.3 82.03,5.18 80.85,6.36 80.85,11.03 81.65,11.83 SW3.3 v1(86.3,11.83) SW3.4 ; J6.21 81.09,29.69 81.8,28.98 86,28.98 v1(86.85,28.13)
  BOTTOM w0.15: v1(86.85,28.13) 86.85,12.38 v1(86.3,11.83)
TL_KEY4: length 32.8
  TOP w0.15: 82.69,25.82 81.36,27.15 J6.23 ; 82.69,25.82 80.95,24.08 80.95,19.13 81.1,18.98 SW6.3 SW6.4 ; 82.69,25.82 SW4.3 SW4.4
TL_PA0: length 56.2
  TOP w0.15: U8.59 39.92,50.88 38.83,49.78 34.7,49.78 v1(29.55,44.63) ; v1(31.15,18.31) 31.12,18.28 20.2,18.28 19.05,19.43 J7.24
  BOTTOM w0.15: v1(29.55,44.63) 32.08,42.11 32.08,32.78 31.18,31.88 31.18,18.33 v1(31.15,18.31)
TL_PA1: length 90
  TOP w0.15: v1(30.38,16.31) 29.88,15.81 19.82,15.81 19.5,15.48 v1(14.5,15.48) ; J7.6 15.06,42.29 14,41.23 v1(14,24.98) ; v1(46.1,40.37) 46.1,40.85 45.6,41.36 45.6,46.63 45.77,46.81 U8.11
  BOTTOM w0.15: v1(30.38,16.31) 30.88,15.81 35.92,15.81 42.44,22.33 42.44,39.83 43.19,40.58 45.81,40.58 46.02,40.37 v1(46.1,40.37) ; v1(14,24.98) 14,15.98 v1(14.5,15.48)
TL_PA2: length 59.7
  TOP w0.15: v1(31.35,16.28) 30.57,15.51 21.27,15.51 20.12,14.35 J7.28 ; 46.17,47.88 46.17,46.73 45.9,46.46 45.9,41.58 46.97,40.51 v1(47.15,40.51)
  BOTTOM w0.15: v1(47.15,40.51) 47.05,40.51 46.54,41.01 42.95,41.01 41.96,40.02 41.96,22.52 35.72,16.28 v1(31.35,16.28)
TL_PA3: length 61.7
  TOP w0.15: J7.30 19.18,11.81 20.52,13.16 27.44,13.16 v1(28.01,13.73) ; v1(47.51,41.23) 47.51,41.69 46.62,42.58 46.62,46.16 46.98,46.51 46.98,47.88
  BOTTOM w0.15: v1(28.01,13.73) 28.01,15.24 29.93,17.16 35.12,17.16 40.92,22.96 40.92,40.46 42.46,41.99 47.03,41.99 47.51,41.51 v1(47.51,41.23)
TL_PA4: length 62.4
  TOP w0.15: v1(46.78,41.52) 46.27,42.03 46.27,46.36 46.58,46.66 U8.13 ; J7.32 19.87,9.27 20.7,10.11 20.7,12.13 21.43,12.86 v1(28.04,12.86)
  BOTTOM w0.15: v1(28.04,12.86) 28.71,13.52 28.71,15.51 30.04,16.85 35.49,16.85 41.4,22.76 41.4,40.26 42.66,41.52 v1(46.78,41.52)
TL_PA5_DM: length 67
  TOP w0.15: v1(40.51,13.94) 40.08,13.51 33.2,13.51 27.93,8.23 21.95,8.23 19.3,5.59 17.19,5.59 17.04,5.73 J7.34 ; v1(45.37,39.56) 45.19,39.74 45.19,46.94 45.38,47.13 U8.10
  BOTTOM w0.15: v1(40.51,13.94) 40.04,13.47 39.29,13.47 38.64,14.12 38.64,16.12 45.23,22.71 45.23,39.42 v1(45.37,39.56)
TL_PA6_DP: length 67.4
  TOP w0.15: v1(44.75,39.56) 44.93,39.74 44.93,47.23 44.98,47.28 44.98,47.88 ; v1(40.56,12.94) 40.25,13.26 33.3,13.26 28.03,7.98 22.05,7.98 19.41,5.34 17.19,5.34 17.04,5.19 J7.36
  BOTTOM w0.15: v1(44.75,39.56) 44.93,39.38 44.93,22.83 38.34,16.24 38.34,14 39.16,13.17 40.34,13.17 v1(40.56,12.94)
TL_PA7_SWS: length 1.7
  TOP w0.2: U8.58 39.3,51.28 R11.1
TL_PB0: length 110.3
  TOP w0.15: U8.1 41.77,45.76 40.75,44.73 40.75,36.59 42.31,35.03 59.38,35.03 v1(60.04,34.36) 60.46,34.79 62.43,34.79 68.46,40.82 72.49,40.82 72.97,40.33 72.97,32.73 74.94,30.76 80.4,30.76 81.42,31.78 v1(83.72,31.78) ; J6.12 67.81,42.39 67.57,42.63 66.31,42.63 64.93,41.26 v1(60.05,41.26)
  BOTTOM w0.15: v1(60.05,41.26) 60.08,41.23 60.08,34.4 v1(60.04,34.36) ; v1(83.72,31.78) 82.12,33.38 82.12,53.61 J3.1 J3.3
TL_PB1: length 75.1
  TOP w0.15: U8.62 40.16,49.68 38.61,48.13 36.17,48.13 35.72,47.68 v1(35.72,47.36) ; J6.14 68.3,39.85 67.43,38.99 67.43,37.08 68.33,36.19 71.61,36.19 72.15,35.64 72.15,34.26 71.46,33.58 67.55,33.58 66.88,32.91 66.88,31.41 65.2,29.73 37.14,29.73 v1(36.66,29.25)
  BOTTOM w0.15: v1(36.66,29.25) 36.17,29.74 36.17,45.01 35.3,45.87 35.3,46.93 v1(35.72,47.36)
TL_PB2: length 66.8
  TOP w0.15: J6.16 71.97,37.31 72.45,36.83 72.45,34.14 71.59,33.28 67.68,33.28 67.18,32.78 67.18,31.29 65.33,29.43 38.15,29.43 37.98,29.26 v1(37.53,29.26) ; U8.63 40.33,49.28 38.88,47.83 36.92,47.83 36.47,47.38 v1(36.47,46.56)
  BOTTOM w0.15: v1(36.47,46.56) 36.47,30.32 v1(37.53,29.26)
TL_PB3: length 63.5
  TOP w0.15: J6.18 68.32,34.77 66.58,33.03 66.58,31.53 65.08,30.03 36.62,30.03 v1(35.82,29.23) ; v1(34.87,48.09) 35.21,48.43 38.34,48.43 39.99,50.08 U8.61
  BOTTOM w0.15: v1(35.82,29.23) 35.82,44.78 34.74,45.86 34.74,47.96 v1(34.87,48.09)
TL_PB4: length 59.7
  TOP w0.15: U8.28 49.58,53.28 49.77,53.08 50.41,53.08 50.6,53.26 v1(50.72,53.26) ; J6.32 67.84,16.99 66.78,15.93 53.95,15.93 52.55,17.33 v1(50.23,17.33)
  BOTTOM w0.15: v1(50.72,53.26) 50.78,53.21 50.78,51.87 51.5,51.15 51.5,29.38 50.23,28.1 v1(50.23,17.33)
TL_PB5: length 59.7
  TOP w0.15: v1(74.48,29.44) 74.48,30.47 72.72,32.23 J6.20 ; v1(51.7,53.71) 51.7,53.61 51.55,53.46 51.55,53.13 51.1,52.68 49.7,52.68 49.5,52.88 U8.27
  BOTTOM w0.15: v1(51.7,53.71) 51.7,53.45 51.12,52.87 51.12,52.03 51.86,51.29 51.86,30.87 54.65,28.08 71.7,28.08 72.93,26.85 73.81,26.85 74.48,27.53 v1(74.48,29.44)
TL_PB6: length 57.9
  TOP w0.15: v1(52.68,53.34) 52.23,53.34 51.27,52.38 49.58,52.38 49.48,52.48 U8.26 ; J6.22 73.46,29.69 v1(73.9,30.13)
  BOTTOM w0.15: v1(73.9,30.13) 73.9,27.37 73.68,27.15 73.13,27.15 71.91,28.38 54.77,28.38 52.17,30.99 52.17,51.43
  BOTTOM w0.2: v1(52.68,53.34) 52.15,53.34 51.55,52.75 51.55,52.1 52.17,51.48 52.17,51.43
TL_PB7: length 50.6
  TOP w0.15: J6.24 72.85,27.15 v1(73.33,27.63) ; U8.25 51.84,52.08 v1(52.12,52.36)
  BOTTOM w0.15: v1(52.12,52.36) 52.5,51.99 52.5,31.08 54.9,28.68 72.28,28.68 v1(73.33,27.63)
TL_PC0_AUDIO_P: length 67.8
  TOP w0.15: v1(51.4,14.83) 52.48,13.76 67.28,13.76 67.97,14.45 J6.34 J6.36 ; U8.36 46.58,55.36 v1(47.05,54.89)
  BOTTOM w0.15: v1(51.4,14.83) 51.08,14.83 48.27,17.63 48.27,31.18 50.42,33.33 50.42,51.07 48.42,53.08 47.35,53.08 46.7,53.72 46.7,54.55 v1(47.05,54.89)
TL_PC1_AUDIO_N: length 74.1
  TOP w0.15: v1(51.35,14.14) 52.03,13.46 67.47,13.46 67.72,13.21 v1(67.72,11.78) ; U8.38 45.77,54.97 v1(46,54.74) ; v1(67.7,7.36) 68.22,6.83 J6.40 J6.38
  BOTTOM w0.15: v1(51.35,14.14) 47.98,17.51 47.98,31.31 50.12,33.46 50.12,50.76 48.1,52.78 47.23,52.78 46.4,53.6 46.4,54.34 v1(46,54.74) ; v1(67.72,11.78) 67.72,7.38 v1(67.7,7.36)
TL_PC2_32K: length 50.6
  TOP w0.15: Y2.1 51.73,63.36 51.3,62.93 R1.1 51.3,61.58 C21.2 50.58,60.31 v1(50.33,60.31) 50.15,60.31 49.48,59.63 49.05,59.63 46.17,56.76 46.17,55.88 ; J6.5 76.95,50.01 78.85,51.91 78.85,58.53 v1(78.03,59.36)
  POWER w0.15: v1(50.33,60.31) 50.33,60.35 50.78,60.8 54.85,60.8 55.27,60.38 71.38,60.38 71.85,60.86 76.53,60.86 v1(78.03,59.36)
TL_PC3_32K: length 55.7
  TOP w0.15: v1(77.3,59.33) 78.47,58.16 78.47,52.08 77.65,51.26 74.95,51.26 74.6,50.91 74.6,48.68 75.81,47.47 J6.7 ; U8.39 45.38,56.48 v1(49.23,60.33) C22.2 50.3,61.41 R1.2 50.3,63.41 50.2,63.51
  POWER w0.15: v1(49.23,60.33) 49.73,59.83 50.62,59.83 51.23,60.43 54.65,60.43 55.07,60.01 71.56,60.01 72.03,60.49 76.15,60.49 v1(77.3,59.33)
TL_PC4_TDI: length 74.5
  TOP w0.15: v1(44.91,54.63) 44.49,54.63 43.77,55.35 U8.43 ; v1(24.6,53.2) 19.97,53.2 17.25,50.48 5.18,50.48 J4.12 ; J6.2 69.47,55.09 68.8,55.76 v1(68.8,56.91)
  POWER w0.15: v1(24.6,53.2) 25.5,52.3 42.07,52.3 43.82,54.06 44.33,54.06 v1(44.91,54.63) 44.91,55.65 46.57,57.31 68.4,57.31 v1(68.8,56.91)
TL_PC5_TDO: length 80.2
  TOP w0.15: U8.44 43.38,55.05 v1(43.86,54.57) ; J6.4 73,52.55 73.33,52.88 73.33,54.66 71.02,56.96 v1(69.7,56.96)
  POWER w0.15: J4.11 20.34,51.85 25.1,56.61 37.17,56.61 40.39,53.38 42.67,53.38 v1(43.86,54.57) 44.42,55.13 44.42,55.63 46.39,57.61 69.05,57.61 v1(69.7,56.96)
TL_PC6_TMS: length 86.1
  TOP w0.15: U8.46 42.58,55.39 42.29,55.11 42.29,54.61 v1(41.96,54.28) ; J6.6 72.68,50.01 73.65,50.98 73.65,54.91 v1(70.91,57.64)
  POWER w0.15: J4.4 5.09,60.73 22.65,60.73 26.17,57.21 37.64,57.21 40.57,54.28 v1(41.96,54.28) 41.96,54.77 42.68,55.5 43.44,55.5 46.14,58.21 70.35,58.21 v1(70.91,57.64)
TL_PC7_TCK: length 88.3
  TOP w0.15: v1(42.79,54.93) 42.98,55.12 42.98,55.88 ; v1(71.78,57.61) 71.78,57.56 73.95,55.38 73.95,48.63 72.79,47.47 J6.8
  POWER w0.15: J4.6 5.04,58.23 24.42,58.23 25.75,56.91 37.43,56.91 40.57,53.77 42.36,53.77 42.79,54.19 v1(42.79,54.93) 43.29,54.93 46.26,57.91 69.9,57.91 70.64,57.17 71.34,57.17 v1(71.78,57.61)
TL_PD0: length 51.9
  TOP w0.15: J6.10 71.85,44.93 73.15,43.63 73.15,41.9 72.43,41.18 68.23,41.18 62.37,35.33 43.25,35.33 41.05,37.53 41.05,44.53 42.17,45.65 42.17,47.88
TL_PD5: length 38.5
  TOP w0.15: v1(26,37.21) 37.02,37.21 v1(37.95,36.28) ; v1(19,35.98) 17.69,34.67 J7.12 ; v1(37.95,48.93) 38.4,48.93 39.95,50.48 U8.60
  BOTTOM w0.15: v1(26,37.21) 24.77,35.98 v1(19,35.98) ; v1(37.95,48.93) v1(37.95,36.28)
TL_PE0: length 26.5
  TOP w0.15: J7.2 17.44,47.37 v1(18.98,48.91) ; v1(22.26,49.74) 23.25,50.73 24.8,50.73 28.15,54.08 U8.51
  BOTTOM w0.15: v1(18.98,48.91) 19.52,49.46 21.98,49.46 v1(22.26,49.74)
TL_PE1: length 28.5
  TOP w0.15: J7.4 17.55,44.83 20.48,47.76 20.48,49.11 22.5,51.13 24.55,51.13 27.9,54.48 U8.50
TL_PE2: length 42.2
  TOP w0.15: U8.55 30.55,52.48 v1(26.7,48.63) ; v1(20.5,46.31) 20.02,45.83 20.02,32.01 17.61,29.59 J7.16
  BOTTOM w0.15: v1(20.5,46.31) 20.5,47.81 21.32,48.63 v1(26.7,48.63)
TL_PE3: length 47.4
  TOP w0.15: J7.20 19.03,24.51 20.98,26.46 20.98,42.8 21.88,43.71 24.73,43.71 25.95,44.93 25.95,48.96 29.88,52.88 U8.54
TL_PE4: length 20.7
  TOP w0.15: J7.1 23.34,48.52 28.5,53.68 U8.52
TL_PE5: length 22.9
  TOP w0.15: U8.53 28.86,53.28 25.48,49.9 25.48,46.46 23.85,44.83 J7.3
TL_PE6: length 21.3
  TOP w0.15: U8.57 35.2,51.68 25.81,42.29 J7.5
TL_PE7: length 32.6
  TOP w0.15: J7.8 v1(19,39.75) ; v1(21.5,38.48) 21.32,38.66 21.32,42.73 21.95,43.36 24.8,43.36 33.52,52.08 U8.56
  BOTTOM w0.15: v1(19,39.75) 20.23,39.75 v1(21.5,38.48)
TL_PF0_MOSI: length 21.9
  TOP w0.15: v1(49.05,41.1) 49.53,40.62 U2.5 ; U8.6 43.77,44.95 42.61,43.78 42.61,38.21 43.86,36.97 v1(46.7,36.97)
  BOTTOM w0.15: v1(46.7,36.97) 46.7,38.77 48.43,40.49 48.43,40.5 49.03,41.1 v1(49.05,41.1)
TL_PF1_MCLK: length 19.8
  TOP w0.15: U2.6 49.26,39.35 v1(49.04,39.57) ; 44.17,47.88 44.17,44.78 43.01,43.62 43.01,38.38 43.89,37.5 v1(48.09,37.5)
  BOTTOM w0.15: v1(48.09,37.5) 48.09,38.63 v1(49.04,39.57)
TL_PF2_MSIO3: length 17.5
  TOP w0.15: U2.7 43.88,38.08 43.41,38.55 43.41,43.45 44.58,44.62 U8.8
TL_PF3_MSCN: length 28
  TOP w0.15: R3.2 57.73,36.81 U2.1 53.74,36.81 53.09,37.47 49.95,37.47 49.27,36.79 47.74,36.79 47.34,36.39 43.87,36.39 42.21,38.05 42.21,43.95 43.38,45.11 U8.5
TL_PF4_MISO: length 29.4
  TOP w0.15: v1(49.04,38.7) 55.13,38.7 55.75,38.08 U2.2 ; 42.98,47.88 42.98,45.28 41.81,44.12 41.81,37.88 43.61,36.09 47.54,36.09 47.84,36.39 48.84,36.39 49.26,35.96 v1(49.26,35.88)
  BOTTOM w0.15: v1(49.26,35.88) 49.26,38.48 v1(49.04,38.7)
TL_PF5_MSIO2: length 31.3
  TOP w0.15: U2.3 55.73,39.35 55.17,39.91 49.53,39.91 v1(49.02,40.42) ; v1(47.99,35.83) 47.89,35.73 43.4,35.73 41.41,37.72 41.41,44.28 42.58,45.44 U8.3
  BOTTOM w0.15: v1(49.02,40.42) 47.38,38.78 47.38,36.44 v1(47.99,35.83)
TL_RFVDD_1P25: length 65.1
  TOP w0.2: U8.49 40.2,54.88 39.92,55.16
  TOP w0.3: 49.33,42.51 64.17,42.51
  TOP w0.35: v1(64.41,42.27) 64.15,42.53 49.36,42.53 v1(49.09,42.27)
  TOP w0.5: 39.92,55.16 38.49,55.16 38.3,55.34 C8.1 36.34,55.34 v1(36.3,55.31) 37.88,55.31 C9.1
  BOTTOM w0.5: J9.13 66.87,39.81 v1(64.41,42.27) ; v1(36.3,55.31) 40.04,51.56 40.04,46.21 41,45.26 46.77,45.26 49.09,42.94 v1(49.09,42.27)
TL_SDMN0: length 28.4
  TOP w0.15: L16.1 11.78,19.51 15.5,23.23 21.5,23.23 22.78,24.51 J7.19
TL_SDMN1: length 43.1
  TOP w0.15: v1(14,48.98) 4.5,48.98 3.2,47.68 L18.1 ; v1(26.25,33.98) 25.56,34.67 J7.11
  BOTTOM w0.15: v1(26.25,33.98) 25.5,33.23 15.25,33.23 14.5,33.98 14.5,48.48 v1(14,48.98)
TL_SDMP0: length 39.8
  TOP w0.15: L15.1 3.72,3.01 5,1.73 12.75,1.73 13.5,2.48 13.5,18.73 15.5,20.73 21.5,20.73 22.8,19.43 J7.23
TL_SDMP1: length 31.6
  TOP w0.15: J7.15 v1(25.75,29.59) ; L17.1 v1(11.28,44.98)
  BOTTOM w0.15: v1(25.75,29.59) 24.61,30.73 14.25,30.73 13.25,31.73 13.25,43.01 v1(11.28,44.98)
TL_VBAT: length 140.9
  TOP w0.2: 50.15,54.28 50,54.28 49.8,54.48 ; 49.8,54.48 51.58,54.48 ; 49.8,54.48 U8.31
  TOP w0.3: R2.2 v1(35.85,11.01)
  TOP w0.5: 56.25,33.08 56.25,32.31 v1(56.27,32.28) 56,32.28 55.2,33.08 ; v1(66.89,44.89) v1(67.67,44.89) ; v1(66.88,54.78) 52.98,54.78 C48.1 51.38,54.28 50.15,54.28
  TOP w1: v1(66.89,44.89) v1(57.2,44.89) v1(56.25,44.89) ; v1(56.27,33.11) 56.25,33.08 v1(30.5,33.08) v1(29.77,33.08)
  BOTTOM w0.5: 29.8,33.11 29.8,24.31 26.7,21.21 26.7,12.26 27.23,11.73 35.12,11.73 v1(35.85,11.01) ; v1(56.27,33.11) v1(56.27,32.28) ; 29.8,34.43 30.5,33.73 v1(30.5,33.08) v1(29.77,33.08) ; J9.9 J9.7 J9.5 J9.3 67.38,52.51 66.88,53.01 v1(66.88,54.78) ; v1(57.2,44.89) 57.17,44.87 56.27,44.87
  BOTTOM w1: v1(56.27,33.11) 56.27,44.87 v1(56.25,44.89) ; v1(66.89,44.89) v1(67.67,44.89) J9.9 ; J8.4 J8.6 25.56,42.27 29.8,38.03 29.8,33.11 v1(29.77,33.08)
